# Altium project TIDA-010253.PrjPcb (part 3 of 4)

## Sheet Driver and output.SchDoc
size 558 x 431 mm; Date: Not shown in title block; ApprovedBy: Not shown in title block; CheckedBy: Not shown in title block; Author: Not shown in title block; CompanyName: Not shown in title block; Engineer: Not shown in title block; Organization: Not shown in title block; Address1: Not shown in title block; Address2: Not shown in title block; Address3: Not shown in title block; Address4: Not shown in title block; DocumentNumber: 1; Revision: Use project parameter SCH_Rev; SheetNumber: 4; SheetTotal: 7; PageSetup: Record=PageOptions¦CenterHorizontal=True¦CenterVertical=True¦PrintScale=1.00¦XCorrection=1.00¦YCorrection=1.00¦PrintKind=0¦BorderSize=5000000¦LeftOffset=0¦BottomOffset=0¦Orientation=2¦PaperLength=1000¦PaperWidth=1000¦Scale=100¦PaperSource=15¦PrintQuality=600¦MediaType=1¦DitherType=10¦PaperKind=Letter¦PrintScaleMode=1
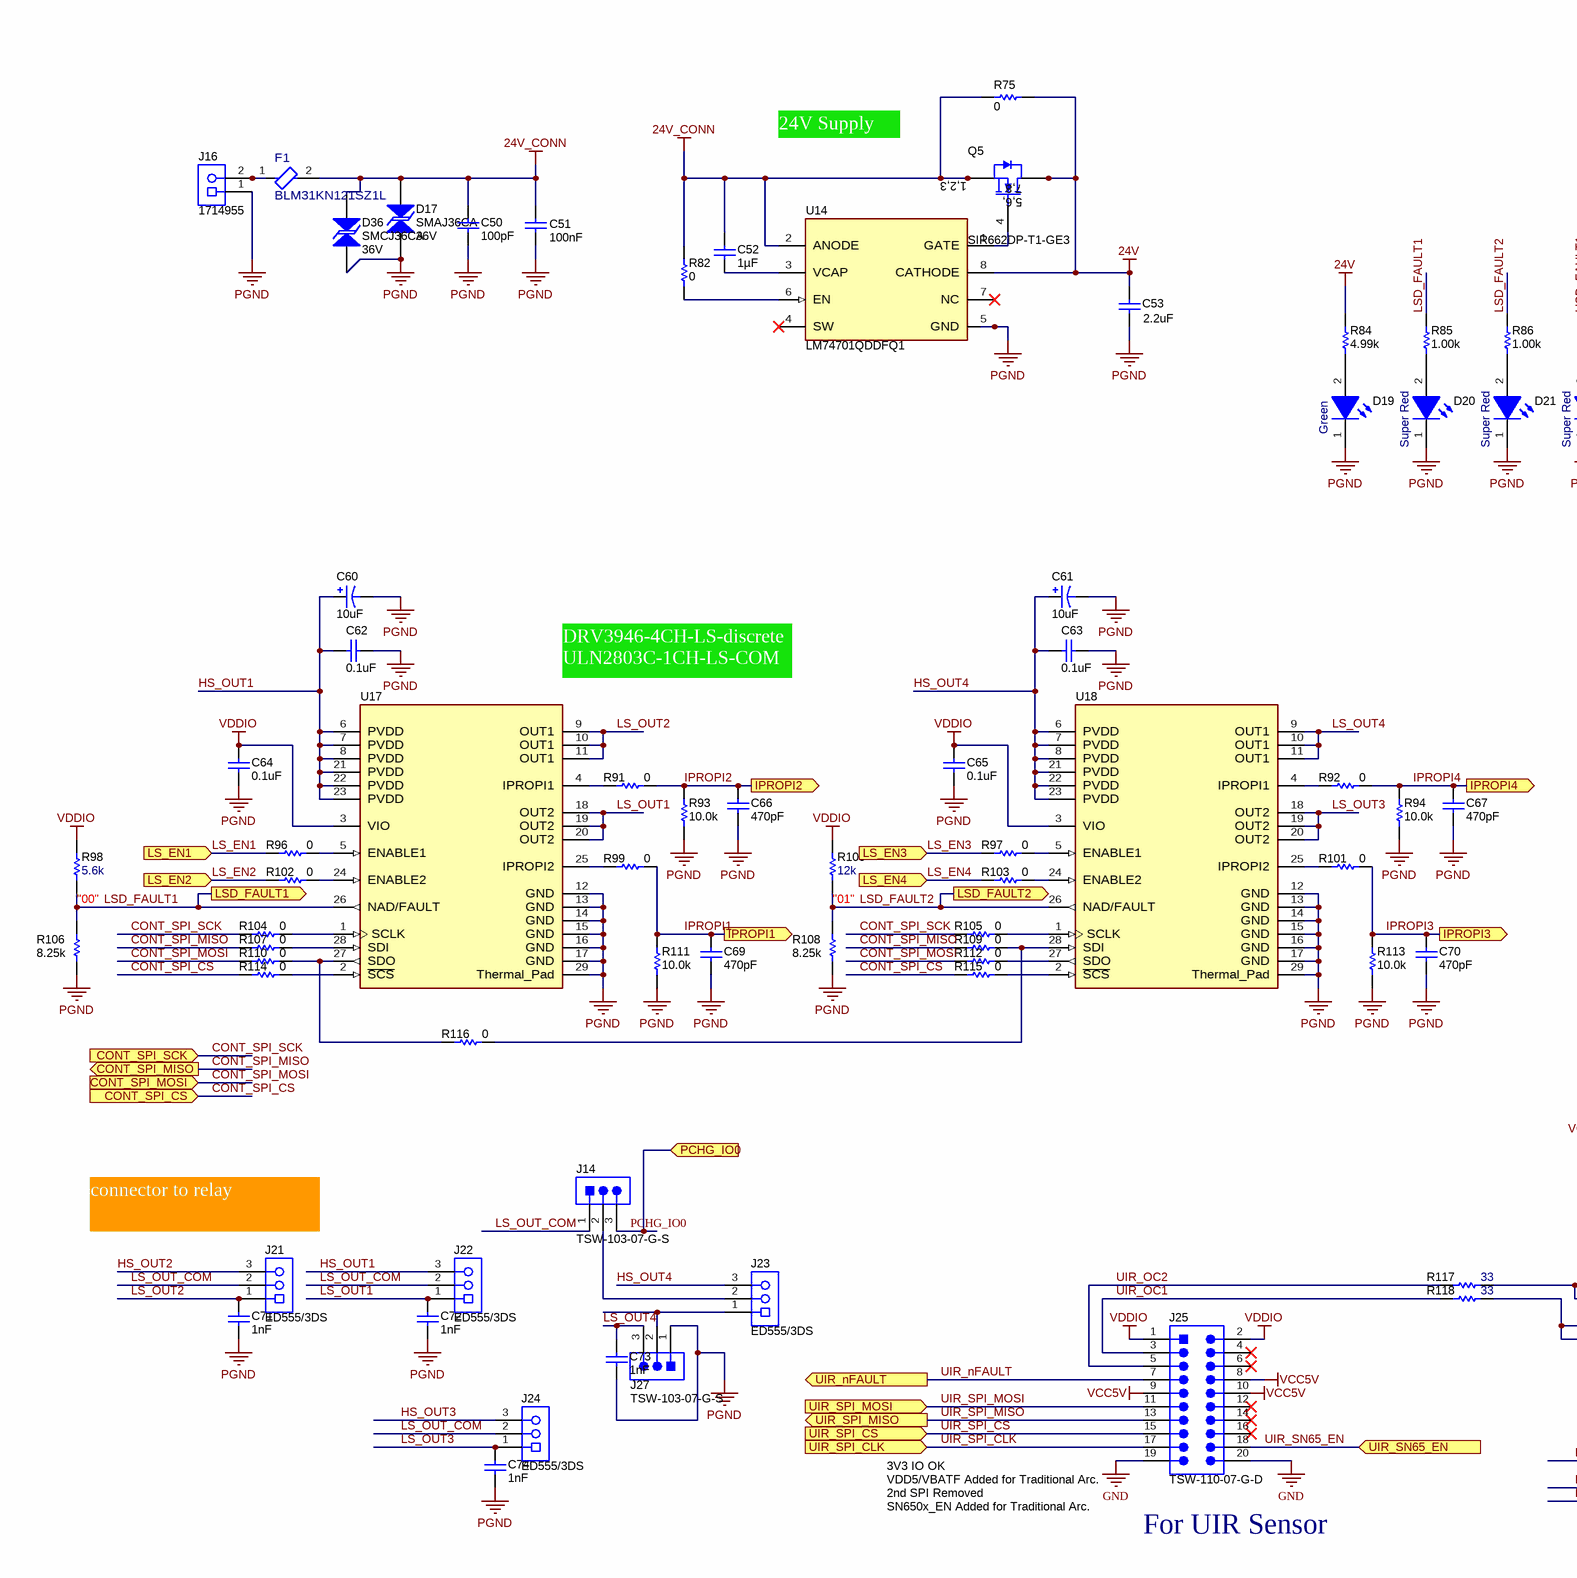
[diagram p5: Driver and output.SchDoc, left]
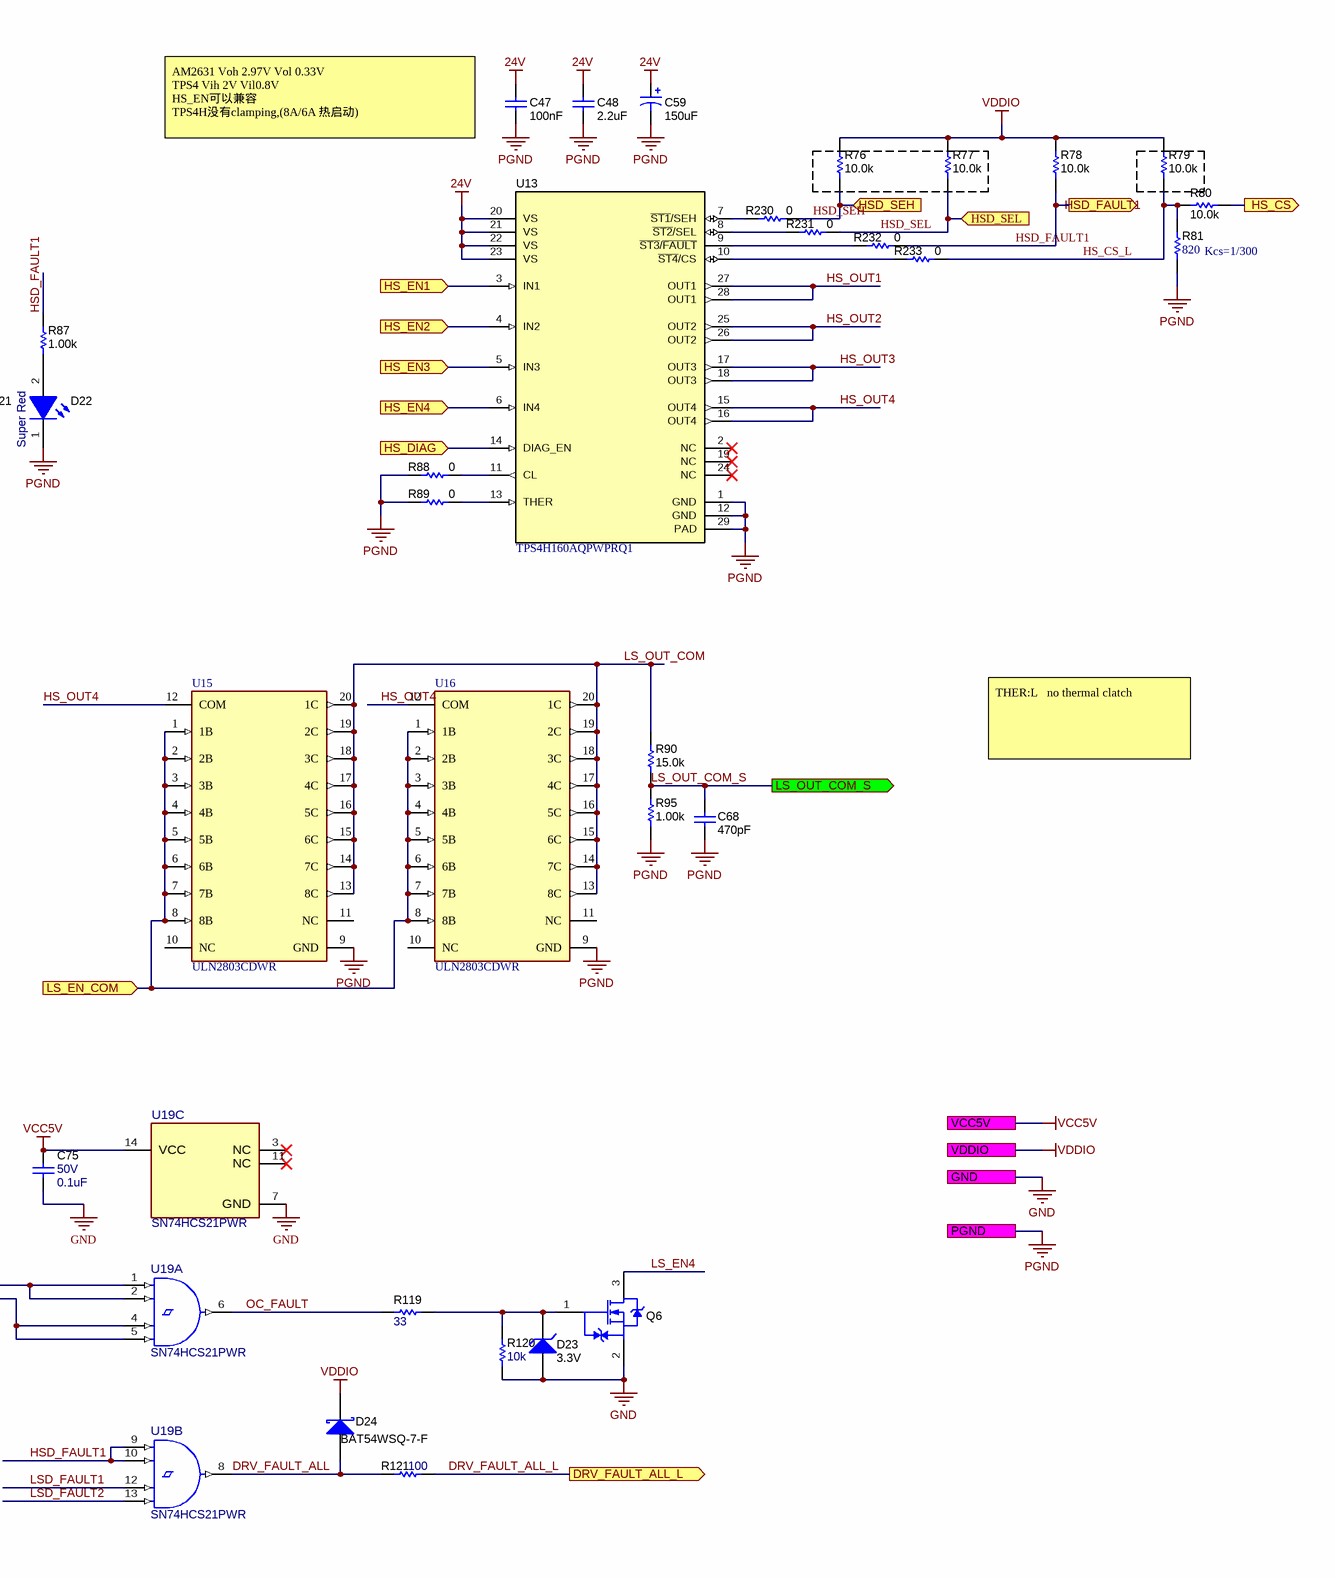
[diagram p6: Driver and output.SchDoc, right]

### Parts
C47  Cap_F: 100nF  [0603L]  (hidden comment: 885012206095)
C48  ValueDisplayed: 2.2uF  [0805L]  (hidden comment: C2012X6S1H225K125AB)
C50  ValueDisplayed: 100pF  [0603L]  (hidden comment: C0603C101J5GAC)
C51  Cap_F: 100nF  [0603L]  (hidden comment: 885012206095)
C52  Cap_F: 1µF  [0603L]  (hidden comment: CGA3E1X7R1E105K080AD)
C53  ValueDisplayed: 2.2uF  [0805L]  (hidden comment: C2012X6S1H225K125AB)
C59  ValueDisplayed: 150uF  [SM_RADIAL_G]  (hidden comment: EEE-FK1H151P)
C60  ValueDisplayed: 10uF  [SM_RADIAL_D]  (hidden comment: EEE-FK1H100P)
C61  ValueDisplayed: 10uF  [SM_RADIAL_D]  (hidden comment: EEE-FK1H100P)
C62  ValueDisplayed: 0.1uF  [0402L]  (hidden comment: C1005X7R1H104K050BE)
C63  ValueDisplayed: 0.1uF  [0402L]  (hidden comment: C1005X7R1H104K050BE)
C64  ValueDisplayed: 0.1uF  [0402L]  (hidden comment: C1005X7R1H104K050BE)
C65  ValueDisplayed: 0.1uF  [0402L]  (hidden comment: C1005X7R1H104K050BE)
C66  ValueDisplayed: 470pF  [0402L]  (hidden comment: GRM155R71H471KA01D)
C67  ValueDisplayed: 470pF  [0402L]  (hidden comment: GRM155R71H471KA01D)
C68  ValueDisplayed: 470pF  [0402L]  (hidden comment: GRM155R71H471KA01D)
C69  ValueDisplayed: 470pF  [0402L]  (hidden comment: GRM155R71H471KA01D)
C70  ValueDisplayed: 470pF  [0402L]  (hidden comment: GRM155R71H471KA01D)
C71  Cap_F: 1nF  [0603L]  (hidden comment: C0603C102J5RACAUTO)
C72  Cap_F: 1nF  [0603L]  (hidden comment: C0603C102J5RACAUTO)
C73  Cap_F: 1nF  [0603L]  (hidden comment: C0603C102J5RACAUTO)
C74  Cap_F: 1nF  [0603L]  (hidden comment: C0603C102J5RACAUTO)
C75  VDC_V: 50V  ValueDisplayed: 0.1uF  [0402]  (hidden comment: GCM155R71H104KE02D)
D17  SMAJ36CA  value 36V  [SMA_Bi]
D19  value Green  [WL-SMCW_GREEN]  (hidden comment: 150060VS75000)
D20  value Super Red  [WL-SMCW_RED]  (hidden comment: 150060SS75000)
D21  value Super Red  [WL-SMCW_RED]  (hidden comment: 150060SS75000)
D22  value Super Red  [WL-SMCW_RED]  (hidden comment: 150060SS75000)
D23  value 3.3V  [SOD-323]  (hidden comment: SZMM3Z3V3ST1G)
D24  BAT54WSQ-7-F  [SOD-323]
D36  SMCJ36CA  value 36V  [SMC_Bi]
F1  BLM31KN121SZ1L  [FP-BLM31KN121SZ1L_1206-MFG]
J14  TSW-103-07-G-S  [TSW-103-07-G-S]
J16  1714955  [Phoenix_1714955]
J21  ED555/3DS  [TERM_BLK_ED555-3DS]
J22  ED555/3DS  [TERM_BLK_ED555-3DS]
J23  ED555/3DS  [TERM_BLK_ED555-3DS]
J24  ED555/3DS  [TERM_BLK_ED555-3DS]
J25  TSW-110-07-G-D  [TSW-110-07-G-D]
J27  TSW-103-07-G-S  [TSW-103-07-G-S]
Q5  SIR662DP-T1-GE3  [PowerPAK_SO-8]
Q6  RJU003N03FRAT106  [SOT-323]  (value not drawn)
R75  ValueDisplayed: 0  [2512]  (hidden comment: RMC1JPTE)
R76  ValueDisplayed: 10.0k  [0402L]  (hidden comment: RC0402FR-0710KL)
R77  ValueDisplayed: 10.0k  [0402L]  (hidden comment: RC0402FR-0710KL)
R78  ValueDisplayed: 10.0k  [0402L]  (hidden comment: RC0402FR-0710KL)
R79  ValueDisplayed: 10.0k  [0402L]  (hidden comment: RC0402FR-0710KL)
R80  ValueDisplayed: 10.0k  [0402L]  (hidden comment: RC0402FR-0710KL)
R81  ValueDisplayed: 820  [0402]  (hidden comment: RC0402FR-07820RL)
R82  ValueDisplayed: 0  [0402L]  (hidden comment: CRCW04020000Z0EDHP)
R84  ValueDisplayed: 4.99k  [0603L]  (hidden comment: CRCW06034K99FKEAC)
R85  ValueDisplayed: 1.00k  [0402L]  (hidden comment: RC0402FR-071KL)
R86  ValueDisplayed: 1.00k  [0402L]  (hidden comment: RC0402FR-071KL)
R87  ValueDisplayed: 1.00k  [0402L]  (hidden comment: RC0402FR-071KL)
R88  ValueDisplayed: 0  [0402L]  (hidden comment: CRCW04020000Z0EDHP)
R89  ValueDisplayed: 0  [0402L]  (hidden comment: CRCW04020000Z0EDHP)
R90  ValueDisplayed: 15.0k  [0402L]  (hidden comment: RC0402FR-0715KL)
R91  ValueDisplayed: 0  [0402L]  (hidden comment: CRCW04020000Z0EDHP)
R92  ValueDisplayed: 0  [0402L]  (hidden comment: CRCW04020000Z0EDHP)
R93  ValueDisplayed: 10.0k  [0402L]  (hidden comment: RC0402FR-0710KL)
R94  ValueDisplayed: 10.0k  [0402L]  (hidden comment: RC0402FR-0710KL)
R95  ValueDisplayed: 1.00k  [0402L]  (hidden comment: RC0402FR-071KL)
R96  ValueDisplayed: 0  [0402L]  (hidden comment: CRCW04020000Z0EDHP)
R97  ValueDisplayed: 0  [0402L]  (hidden comment: CRCW04020000Z0EDHP)
R98  ValueDisplayed: 5.6k  [0402L]  (hidden comment: CRCW04025K60JNED)
R99  ValueDisplayed: 0  [0402L]  (hidden comment: CRCW04020000Z0EDHP)
R100  ValueDisplayed: 12k  [0402L]  (hidden comment: CRCW040212K0JNED)
R101  ValueDisplayed: 0  [0402L]  (hidden comment: CRCW04020000Z0EDHP)
R102  ValueDisplayed: 0  [0402L]  (hidden comment: CRCW04020000Z0EDHP)
R103  ValueDisplayed: 0  [0402L]  (hidden comment: CRCW04020000Z0EDHP)
R104  ValueDisplayed: 0  [0402L]  (hidden comment: CRCW04020000Z0EDHP)
R105  ValueDisplayed: 0  [0402L]  (hidden comment: CRCW04020000Z0EDHP)
R106  ValueDisplayed: 8.25k  [0402L]  (hidden comment: CRCW04028K25FKED)
R107  ValueDisplayed: 0  [0402L]  (hidden comment: CRCW04020000Z0EDHP)
R108  ValueDisplayed: 8.25k  [0402L]  (hidden comment: CRCW04028K25FKED)
R109  ValueDisplayed: 0  [0402L]  (hidden comment: CRCW04020000Z0EDHP)
R110  ValueDisplayed: 0  [0402L]  (hidden comment: CRCW04020000Z0EDHP)
R111  ValueDisplayed: 10.0k  [0402L]  (hidden comment: RC0402FR-0710KL)
R112  ValueDisplayed: 0  [0402L]  (hidden comment: CRCW04020000Z0EDHP)
R113  ValueDisplayed: 10.0k  [0402L]  (hidden comment: RC0402FR-0710KL)
R114  ValueDisplayed: 0  [0402L]  (hidden comment: CRCW04020000Z0EDHP)
R115  ValueDisplayed: 0  [0402L]  (hidden comment: CRCW04020000Z0EDHP)
R116  ValueDisplayed: 0  [0402L]  (hidden comment: CRCW04020000Z0EDHP)
R117  ValueDisplayed: 33  [0402]  (hidden comment: CRCW040233R0JNED)
R118  ValueDisplayed: 33  [0402]  (hidden comment: CRCW040233R0JNED)
R119  ValueDisplayed: 33  [0402]  (hidden comment: CRCW040233R0JNED)
R120  ValueDisplayed: 10k  [0402]  (hidden comment: CRCW040210K0JNED)
R121  ValueDisplayed: 100  [0402]  (hidden comment: CRCW0402100RJNED)
R230  ValueDisplayed: 0  [0402L]  (hidden comment: CRCW04020000Z0EDHP)
R231  ValueDisplayed: 0  [0402L]  (hidden comment: CRCW04020000Z0EDHP)
R232  ValueDisplayed: 0  [0402L]  (hidden comment: CRCW04020000Z0EDHP)
R233  ValueDisplayed: 0  [0402L]  (hidden comment: CRCW04020000Z0EDHP)
U13  TPS4H160AQPWPRQ1  [PWP0028C_N]
U14  LM74701QDDFQ1  [DDF0008A-MFG]
U15  ULN2803CDWR  [FP-DW0020A-MFG]
U16  ULN2803CDWR  [FP-DW0020A-MFG]
U17  DRV3946-Q1  [PWP0028R-MFG]  (value not drawn)
U18  DRV3946-Q1  [PWP0028R-MFG]  (value not drawn)
U19  SN74HCS21PWR  [PW0014A-MFG]  (parts A,B,C of 3)

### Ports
CONT_SPI_CS (in), CONT_SPI_MISO (out), CONT_SPI_MOSI (in), CONT_SPI_SCK (in), DRV_FAULT_ALL_L (out), GND, HS_CS (out), HS_DIAG (in), HS_EN1 (in), HS_EN2 (in), HS_EN3 (in), HS_EN4 (in), HSD_FAULT1 (out), HSD_SEH (in), HSD_SEL (in), IPROPI1 (out), IPROPI2 (out), IPROPI3 (out), IPROPI4 (out), LS_EN1 (in), LS_EN2 (in), LS_EN3 (in), LS_EN4 (in), LS_EN_COM (in), LS_OUT_COM_S (out), LSD_FAULT1 (out), LSD_FAULT2 (out), PCHG_IO0 (in), PGND, UIR_nFAULT (out), UIR_SN65_EN (in), UIR_SPI_CLK (in), UIR_SPI_CS (in), UIR_SPI_MISO (out), UIR_SPI_MOSI (in), VCC5V, VDDIO

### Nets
24V: C47.1 C48.1 C53.1 C59.1(+) Q5.5(D) Q5.6(D) Q5.7(D) Q5.8(D) Q5.9(D) R75.2 R84.2 U13.20(VS) U13.21(VS) U13.22(VS) U13.23(VS) U14.8(CATHODE)
24V_CONN: C50.1 C51.1 C52.1 D17.2 D36.2 F1.2 Q5.1(S) Q5.2(S) Q5.3(S) R75.1 R82.2 U14.2(ANODE)
GND: C75.2 D23.2(A) J25.19 J25.20 Q6.2(S) R120.1 U19.7(GND) ; port GND
PGND: C47.2 C48.2 C50.2 C51.2 C53.2 C59.2(-) C60.2(-) C61.2(-) C62.1 C63.1 C64.2 C65.2 C66.2 C67.2 C68.2 C69.2 C70.2 C71.1 C72.1 C73.1 C74.1 D17.1 D19.1(K) D20.1(K) D21.1(K) D22.1(K) D36.1 J16.1 J27.1 R81.1 R88.1 R89.1 R93.1 R94.1 R95.1 R106.1 R108.1 R111.1 R113.1 U13.1(GND) U13.12(GND) U13.29(PAD) U14.5(GND) U15.9(GND) U16.9(GND) U17.12(GND) U17.13(GND) U17.14(GND) U17.15(GND) U17.16(GND) U17.17(GND) U17.29(Thermal_Pad) U18.12(GND) U18.13(GND) U18.14(GND) U18.15(GND) U18.16(GND) U18.17(GND) U18.29(Thermal_Pad) ; port PGND
VCC5V: C75.1 J25.8 J25.9 J25.10 U19.14(VCC) ; port VCC5V
VDDIO: C64.1 C65.1 D24.1(K) J25.1 J25.2 R76.2 R77.2 R78.2 R79.2 R98.2 R100.2 U17.3(VIO) U18.3(VIO) ; port VDDIO
CONT_SPI_CS: R114.1 R115.1 ; port CONT_SPI_CS
CONT_SPI_MISO: R107.1 R109.1 ; port CONT_SPI_MISO
CONT_SPI_MOSI: R110.1 R112.1 ; port CONT_SPI_MOSI
CONT_SPI_SCK: R104.1 R105.1 ; port CONT_SPI_SCK
DRV_FAULT_ALL: D24.2(A) R121.1 U19.8(2Y)
DRV_FAULT_ALL_L: R121.2 ; port DRV_FAULT_ALL_L
HS_CS: R80.1 ; port HS_CS
HS_CS_L: R79.1 R80.2 R81.2 R233.2
HS_DIAG: U13.14(DIAG_EN) ; port HS_DIAG
HS_EN1: U13.3(IN1) ; port HS_EN1
HS_EN2: U13.4(IN2) ; port HS_EN2
HS_EN3: U13.5(IN3) ; port HS_EN3
HS_EN4: U13.6(IN4) ; port HS_EN4
HS_OUT1: C60.1(+) C62.2 J22.3 U13.27(OUT1) U13.28(OUT1) U17.6(PVDD) U17.7(PVDD) U17.8(PVDD) U17.21(PVDD) U17.22(PVDD) U17.23(PVDD)
HS_OUT2: J21.3 U13.25(OUT2) U13.26(OUT2)
HS_OUT3: J24.3 U13.17(OUT3) U13.18(OUT3)
HS_OUT4: C61.1(+) C63.2 J23.3 U13.15(OUT4) U13.16(OUT4) U15.12(COM) U16.12(COM) U18.6(PVDD) U18.7(PVDD) U18.8(PVDD) U18.21(PVDD) U18.22(PVDD) U18.23(PVDD)
HSD_FAULT1: R78.1 R87.2 R232.2 U19.9(2A) U19.10(2B) ; port HSD_FAULT1
HSD_SEH: R76.1 R230.2 ; port HSD_SEH
HSD_SEL: R77.1 R231.2 ; port HSD_SEL
IPROPI1: C69.1 R99.2 R111.2 ; port IPROPI1
IPROPI2: C66.1 R91.2 R93.2 ; port IPROPI2
IPROPI3: C70.1 R101.2 R113.2 ; port IPROPI3
IPROPI4: C67.1 R92.2 R94.2 ; port IPROPI4
LS_EN1: R96.1 ; port LS_EN1
LS_EN2: R102.1 ; port LS_EN2
LS_EN3: R97.1 ; port LS_EN3
LS_EN4: Q6.3(D) R103.1 ; port LS_EN4
LS_EN_COM: U15.1(1B) U15.2(2B) U15.3(3B) U15.4(4B) U15.5(5B) U15.6(6B) U15.7(7B) U15.8(8B) U16.1(1B) U16.2(2B) U16.3(3B) U16.4(4B) U16.5(5B) U16.6(6B) U16.7(7B) U16.8(8B) ; port LS_EN_COM
LS_OUT1: C72.2 J22.1 U17.18(OUT2) U17.19(OUT2) U17.20(OUT2)
LS_OUT2: C71.2 J21.1 U17.9(OUT1) U17.10(OUT1) U17.11(OUT1)
LS_OUT3: C74.2 J24.1 U18.18(OUT2) U18.19(OUT2) U18.20(OUT2)
LS_OUT4: C73.2 J27.3 U18.9(OUT1) U18.10(OUT1) U18.11(OUT1)
LS_OUT_COM: J14.1 J21.2 J22.2 J24.2 R90.2 U15.13(8C) U15.14(7C) U15.15(6C) U15.16(5C) U15.17(4C) U15.18(3C) U15.19(2C) U15.20(1C) U16.13(8C) U16.14(7C) U16.15(6C) U16.16(5C) U16.17(4C) U16.18(3C) U16.19(2C) U16.20(1C)
LS_OUT_COM_S: C68.1 R90.1 R95.2 ; port LS_OUT_COM_S
LSD_FAULT1: R85.2 R98.1 R106.2 U17.26(NAD/FAULT) U19.12(2C) ; port LSD_FAULT1
LSD_FAULT2: R86.2 R100.1 R108.2 U18.26(NAD/FAULT) U19.13(2D) ; port LSD_FAULT2
OC_FAULT: R119.2 U19.6(1Y)
PCHG_IO0: J14.3 ; port PCHG_IO0
UIR_nFAULT: J25.7 ; port UIR_nFAULT
UIR_OC1: J25.3 R118.1
UIR_OC2: J25.5 R117.1
UIR_SN65_EN: J25.18 ; port UIR_SN65_EN
UIR_SPI_CLK: J25.17 ; port UIR_SPI_CLK
UIR_SPI_CS: J25.15 ; port UIR_SPI_CS
UIR_SPI_MISO: J25.13 ; port UIR_SPI_MISO
UIR_SPI_MOSI: J25.11 ; port UIR_SPI_MOSI
NetC52_2: C52.2 U14.3(VCAP)
NetD19_2: D19.2(A) R84.1
NetD20_2: D20.2(A) R85.1
NetD21_2: D21.2(A) R86.1
NetD22_2: D22.2(A) R87.1
NetD23_1: D23.1(K) Q6.1(G) R119.1 R120.2
NetF1_1: F1.1 J16.2
NetJ14_2: J14.2 J23.2
NetJ23_1: J23.1 J27.2
NetQ5_4: Q5.4(G) U14.1(GATE)
NetR82_1: R82.1 U14.6(EN)
NetR88_2: R88.2 U13.11(CL)
NetR89_2: R89.2 U13.13(THER)
NetR91_1: R91.1 U17.4(IPROPI1)
NetR92_1: R92.1 U18.4(IPROPI1)
NetR96_2: R96.2 U17.5(ENABLE1)
NetR97_2: R97.2 U18.5(ENABLE1)
NetR99_1: R99.1 U17.25(IPROPI2)
NetR101_1: R101.1 U18.25(IPROPI2)
NetR102_2: R102.2 U17.24(ENABLE2)
NetR103_2: R103.2 U18.24(ENABLE2)
NetR104_2: R104.2 U17.1(SCLK)
NetR105_2: R105.2 U18.1(SCLK)
NetR107_2: R107.2 U17.28(SDI)
NetR109_2: R109.2 R116.2 U18.28(SDI)
NetR110_2: R110.2 R116.1 U17.27(SDO)
NetR112_2: R112.2 U18.27(SDO)
NetR114_2: R114.2 U17.2(~{SCS})
NetR115_2: R115.2 U18.2(~{SCS})
NetR117_2: R117.2 U19.1(1A) U19.2(1B)
NetR118_2: R118.2 U19.4(1C) U19.5(1D)
NetR230_1: R230.1 U13.7(~{ST1}/SEH)
NetR231_1: R231.1 U13.8(~{ST2}/SEL)
NetR232_1: R232.1 U13.9(~{ST3}/~{FAULT})
NetR233_1: R233.1 U13.10(~{ST4}/CS)

Not connected (* = marked no-connect by the designer): J25 4* 6* 12* 14* 16*; U13 2(NC)* 19(NC)* 24(NC)*; U14 4(SW)* 7(NC)*; U15 10(NC) 11(NC); U16 10(NC) 11(NC); U19 3(NC)* 11(NC)*

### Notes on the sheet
- 24V Supply
- (near C47) AM2631 Voh 2.97V Vol 0.33V
  TPS4 Vih 2V Vil0.8V
  HS_EN可以兼容
  TPS4H没有clamping,(8A/6A 热启动)
- Kcs=1/300
- DRV3946-4CH-LS-discrete
  ULN2803C-1CH-LS-COM
- THER:L   no thermal clatch
- (near R98) "00"
- (near R100) "01"
- (near J21) connector to relay
- 3V3 IO OK
- 2nd SPI Removed
- VDD5/VBATF Added for Traditional Arc.
- SN650x_EN Added for Traditional Arc.
- (near J25) For UIR Sensor

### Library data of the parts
C47 C51 = CMP-0006837-4: CAP, CERM, 0.1 uF, 50 V, +/- 10%, X7R, 0603; Manufacturer: Wurth Elektronik; TaMin_C: -55°C; Polarized: N; SizeAreaWB_mm2: 4.68; Value1: Unknown; U/M: EA; Value: 0.1uF; TaMax_C: 125°C; SizeZ_mm: 1; SizeX_mm: 1.6; SizeY_mm: 0.8; Cap_Case: 0603; Value2: 50V; SizeArea_mm2: 1.28; AEC Category: Q200
C48 C53 = CMP-0007857-1: CAP, CERM, 2.2 uF, 50 V, +/- 10%, X6S, 0805; Manufacturer: TDK; TaMin_C: -55°C; ESR_ohm: 3.66m; Polarized: N; SizeAreaWB_mm2: 6.75; Value1: 0.00366 ohm; U/M: EA; Value: 2.2uF; TaMax_C: 105°C; SizeZ_mm: 1.45; SizeX_mm: 2; SizeY_mm: 1.25; Cap_Case: 0805; Value2: 50V; SizeArea_mm2: 2.5; Cap_F: 2.2µF; IRMS_A: 3.41207A; AEC Category: Q200
C50 = CMP-0006840-4: CAP, CERM, 100 pF, 50 V, +/- 5%, C0G/NP0, 0603; Manufacturer: Kemet; TaMin_C: -55°C; Polarized: N; SizeAreaWB_mm2: 4.68; Value1: Unknown; U/M: EA; Value: 100pF; TaMax_C: 125°C; SizeZ_mm: 1; SizeX_mm: 1.6; SizeY_mm: 0.8; Cap_Case: 0603; Value2: 50V; SizeArea_mm2: 1.28; AEC Category: Q200
C52 = CMP-0082523-1: CAP, CERM, 1 µF, 25 V,+/- 10%, X7R, AEC-Q200 Grade 1, 0603; Manufacturer: TDK; SizeAreaWB_mm2: 4.68; SizeArea_mm2: 1.28; AEC Qualified: Y; AEC Category: Q200; Value: 1uF; TaMax_C: 125°C; SizeZ_mm: 1; Polarized: N; TaMin_C: -55°C; VDC_V: 25V; SizeY_mm: 0.8; U/M: EA; SizeX_mm: 1.6; Cap_Case: 0603
C59 = CMP-0011178-2: CAP, AL, 150 uF, 50 V, +/- 20%, 0.18 ohm, AEC-Q200 Grade 2, SMD; Manufacturer: Panasonic; TaMin_C: -55°C; ESR_ohm: 0.18; Polarized: Y; SizeAreaWB_mm2: 172.2; U/M: EA; Value: 150uF; TaMax_C: 105°C; SizeZ_mm: 10.2; SizeX_mm: 12; SizeY_mm: 10.3; Cap_Case: G; Value2: 50V; SizeArea_mm2: 123.6; CompType: Capacitor; Cap_F: 150µF; IRMS_A: 670mA; AEC Grade: 2; AEC Category: Q200
C60 C61 = CMP-0011175-2: CAP, AL, 10 uF, 50 V, +/- 20%, 0.88 ohm, AEC-Q200 Grade 2, SMD; Manufacturer: Panasonic; TaMin_C: -55°C; ESR_ohm: 0.88; Polarized: Y; SizeAreaWB_mm2: 84.28; U/M: EA; Value: 10uF; TaMax_C: 105°C; SizeZ_mm: 5.4; SizeX_mm: 7.8; SizeY_mm: 6.6; Cap_Case: D; Value2: 50V; SizeArea_mm2: 51.48; CompType: Capacitor; Cap_F: 10µF; IRMS_A: 165mA; AEC Grade: 2; AEC Category: Q200
C62-C65 = CMP-0064946-2: CAP, CERM, 0.1 uF, 50 V,+/- 10%, X7R, 0402; Manufacturer: TDK; TaMin_C: -55°C; Polarized: N; SizeAreaWB_mm2: 3; Value1: Unknown; U/M: EA; Value: 0.1uF; TaMax_C: 125°C; SizeZ_mm: 0.6; SizeX_mm: 1; SizeY_mm: 0.5; Cap_Case: 0402; Value2: 50V; Cap_F: 100nF; AEC Category: Q200
C66-C70 = CMP-0006691-2: CAP, CERM, 470 pF, 50 V, +/- 10%, X7R, 0402; Manufacturer: MuRata; TaMin_C: -55°C; Polarized: N; SizeAreaWB_mm2: 3; Value1: Unknown; U/M: EA; Value: 470pF; TaMax_C: 125°C; SizeZ_mm: 0.6; SizeX_mm: 1; SizeY_mm: 0.5; Cap_Case: 0402; Value2: 50V; AEC Category: Q200
C71-C74 = CMP-0006844-4: CAP, CERM, 1000 pF, 50 V, +/- 5%, X7R, AEC-Q200 Grade 1, 0603; Manufacturer: Kemet; TaMin_C: -55°C; Polarized: N; SizeAreaWB_mm2: 4.68; Value1: Unknown; U/M: EA; Value: 1000pF; TaMax_C: 125°C; SizeZ_mm: 1; SizeX_mm: 1.6; SizeY_mm: 0.8; Cap_Case: 0603; Value2: 50V; SizeArea_mm2: 1.28; AEC Qualified: Y; AEC Category: Q200
C75 = CMP-0006356-2: CAP, CERM, 0.1 uF, 50 V, +/- 10%, X7R, AEC-Q200 Grade 1, 0402; Manufacturer: MuRata; TaMin_C: -55°C; Polarized: N; SizeAreaWB_mm2: 3; Value1: Unknown; U/M: EA; Value: 0.1uF; TaMax_C: 125°C; SizeZ_mm: 0.6; SizeX_mm: 1; SizeY_mm: 0.5; AEC Qualified: Y; Cap_F: 100nF; AEC Category: Q200
D17 = CMP-0085017-1: Diode, TVS, Bi, 36 V, 58.1 Vc, 400 W, 6.9 A, SMA (non-polarized); Manufacturer: Littelfuse; RJA_CperW: 120; SizeAreaWB_mm2: 32.368125; Vbr_Min: 40V; AEC Qualified: N; SizeArea_mm2: 13.068125; Vc: 58.1V; SizeZ_mm: 2.65; Ipp: 6.9A; AEC Category: Q101; SizeY_mm: 2.575; SizeX_mm: 5.075; Ppk: 400W; Vbr_Max: 44.2V
D19 = CMP-0002894-2: LED, Green, SMD; Manufacturer: Wurth Elektronik; Type: AlInGaP; Value2: 2V; Io_A: 20mA; Value1: W
D20-D22 = CMP-0002893-1: LED, Super Red, SMD; Manufacturer: Wurth Elektronik; Io_A: 20mA; Value1: W; U/M: EA; Vf_V: 1.9V; Type: AlInGaP
D23 = CMP-0085730-1: Diode, Zener, 3.3 V, 300 mW, AEC-Q101, SOD-323; Manufacturer: ON Semiconductor; RJA_CperW: 416; AEC Qualified: Y; SizeArea_mm2: 3.645; SizeX_mm: 2.7; SizeY_mm: 1.35; SizeZ_mm: 1; AEC Category: Q101; SizeAreaWB_mm2: 8.695; Power_W: 300mW; Value1: 0.3W
D24 = CMP-0081199-2: Diode, Schottky, 30 V, 0.1 A, AEC-Q101, SOD-323; Manufacturer: Diodes Inc.; Value1: 0.1A; SizeArea_mm2: 3.645; Value: 30V; Vf_V: 1V; Io_A: 100mA; TJmax_C: 150°C; SizeY_mm: 1.35; SizeX_mm: 2.7; AEC Qualified: Y; SizeAreaWB_mm2: 8.695; SizeZ_mm: 1; AEC Category: Q101
D36 = CMP-0005697-3: Diode, TVS, Bi, 36 V, 58.1 Vc, SMC; Manufacturer: Littelfuse; Ppk: 1.5kW; Vbr_Min: 40V; SizeX_mm: 8.13; SizeZ_mm: 2.6; SizeAreaWB_mm2: 83.2686; RJA_CperW: 75; AEC Category: Q101; Vbr_Max: 44.2V; SizeArea_mm2: 50.5686; Ipp: 25.9A; Vc: 58.1V; AEC Qualified: N; Value1: 1500W; SizeY_mm: 6.22
F1 = CMP-0091575-1: Chip Ferrite Bead, 1206, 120Ω @ 100MHz, 0.009Ω, 25%, 6A; Manufacturer: Murata; SizeZ_mm: 1.8mm; DCR_ohm: 9m; AEC Grade: Grade 1; AEC Qualified: Yes
J14 J27 = CMP-0075407-2: Header, 100mil, 3x1, Gold, TH; Manufacturer: Samtec; Pitch_mm: 2.54; Cert_VDE: N; Gender: Male; Cert_CSA: Y; Voltage_V: 550V; Green_REACh: Passed; Current_A: 6.3A; Green_Lifecycle: Active; Row_Count: 1
J16 = CMP-0055505-1: Terminal Block, 2x1, 6.35mm, Green, TH; Manufacturer: Phoenix Contact; CNHeader: FALSE; Shrouded: Y; Gender: Female; Row_Count: 1; Pitch_mm: 6.35; CT: TRUE
J21-J24 = CMP-0074916-1: Terminal Block, 3.5mm Pitch, 3x1, TH; Manufacturer: On-Shore Technology; Cert_VDE: Y; CNHeader: False; Current_A: 6A; Green_Lifecycle: Active; Shrouded: N; Gender: Female; Green_REACh: Passed; Voltage_V: 150V; Row_Count: 1; Pitch_mm: 3.5; ContactFinish: Brass; CT: True
J25 = CMP-0075421-2: Header, 100mil, 10x2, Gold, TH; Manufacturer: Samtec; Pitch_mm: 2.54; Cert_VDE: N; Gender: Male; Cert_CSA: Y; Voltage_V: 550V; Green_REACh: Passed; Current_A: 6.3A; Green_Lifecycle: Active; Row_Count: 2
Q5 = CMP-0000870-1: MOSFET, N-CH, 60 V, 60 A, PowerPAK SO-8; Alternate Manufacturer: None; Manufacturer: Vishay-Semiconductor; SizeZ_mm: 1.12; ChType: N; Value2: 96 nC; Value1: 0.002; VdsMax_V: 60V; SizeX_mm: 5.99; SizeY_mm: 4.9; Vgs_V: 2.5V; Value: 60V; Rdson45_ohm: 2.7m; SizeArea_mm2: 29.351; AEC Category: Q101; IdsMax_A: 60A; SizeAreaWB_mm2: 55.131; U/M: EA; QgTyp_nC: 96
Q6 = CMP-0067562-1: MOSFET, N-CH, 30 V, 0.3 A, AEC-Q101, SOT-323; Alternate Manufacturer: None; Manufacturer: Rohm; Rdson45_ohm: 1.1; SizeAreaWB_mm2: 10.24; Vgs_V: 12V; Value1: 1.1 ohm; VdsMax_V: 30V; U/M: EA; Value: 30V; IdsMax_A: 3dA; SizeX_mm: 2.2; Value2: ? nC; SizeArea_mm2: 4.84; ChType: N; AEC Qualified: Y; AEC Category: Q101
R75 = CMP-0080698-1: RES, 0, 0%, 1 W, AEC-Q200 Grade 0, 2512; Manufacturer: Kamaya; SizeAreaWB_mm2: 43.16; SizeArea_mm2: 20.16; AEC Qualified: Y; AEC Category: Q200; Value: 0; SizeZ_mm: 0.71; SizeY_mm: 3.2; Power_W: 1W; SizeX_mm: 6.3
R76-R80 R93 R94 R111 R113 = CMP-0078669-1: RES, 10.0 k, 1%, 0.063 W, 0402; Manufacturer: Yageo America; Power_W: 63mW; Green_Lifecycle: Active; TempCo: 100 ppm/C; Value_Code: 10k0; Green_REACh: Passed; Value: 10.0k; EIA_Code: E96; Res_ohm: 10k; SizeX_mm: 1; SizeY_mm: 0.5; SizeZ_mm: 0.6; Value2: 0.063W; AEC Qualified: N; AEC Category: Q200
R81 = CMP-0026743-1: RES, 820, 1%, 0.063 W, 0402; Manufacturer: Yageo America; Power_W: 63mW; TempCo: 100 ppm/C; Value_Code: 820R; U/M: EA; Value: 820; SizeX_mm: 1; SizeY_mm: 0.5; SizeZ_mm: 0.6; Value2: 0.063W; AEC Qualified: N; VDC_V: 50V; AEC Category: Q200
R82 R88 R89 R91 R92 R96 R97 R99 R101-R105 R107 R109 R110 R112 R114-R116 R230-R233 = CMP-0081856-1: RES, 0, 0%, 0.2 W, AEC-Q200 Grade 0, 0402; Manufacturer: Vishay-Dale; SizeAreaWB_mm2: 3; SizeArea_mm2: 0.5; AEC Qualified: Y; AEC Category: Q200; Value: 0; SizeZ_mm: 0.6; Power_W: 200mW; VDC_V: 50V; Value2: 0.2W; SizeX_mm: 1
R84 = CMP-0082533-1: RES, 4.99 k, 1%, 0.1 W, 0603; Manufacturer: Vishay-Dale; Power_W: 100mW; TempCo: 100 ppm/C; SizeAreaWB_mm2: 4.68; Value_Code: 4k99; Value: 4.99k; EIA_Code: E96; SizeX_mm: 1.6; SizeY_mm: 0.8; SizeZ_mm: 1; Value2: 0.1W; SizeArea_mm2: 1.28; AEC Qualified: N; VDC_V: 75V; AEC Category: Q200
R85-R87 R95 = CMP-0026725-1: RES, 1.00 k, 1%, 0.0625 W, 0402; Manufacturer: Yageo America; Power_W: 62.5mW; TempCo: 100 ppm/C; Value_Code: 1k00; U/M: EA; Value: 1.00k; EIA_Code: E96; Res_ohm: 1k; SizeX_mm: 1; SizeY_mm: 0.5; SizeZ_mm: 0.6; AEC Qualified: N; VDC_V: 50V; AEC Category: Q200
R90 = CMP-0078583-1: RES, 15.0 k, 1%, 0.063 W, 0402; Manufacturer: Yageo America; Power_W: 63mW; Green_Lifecycle: Active; TempCo: 100 ppm/C; Value_Code: 15k0; Green_REACh: Passed; Value: 15.0k; EIA_Code: E96; Res_ohm: 15k; SizeX_mm: 1; SizeY_mm: 0.5; SizeZ_mm: 0.6; Value2: 0.063W; AEC Qualified: N; AEC Category: Q200
R98 = CMP-0026952-5: RES, 5.6 k, 5%, 0.063 W, AEC-Q200 Grade 0, 0402; Manufacturer: Vishay-Dale; Power_W: 63mW; TempCo: 200 ppm/C; Value_Code: 5k60; Value: 5.6k; EIA_Code: E24; SizeX_mm: 1; SizeY_mm: 0.5; SizeZ_mm: 0.6; Value2: 0.063W; AEC Qualified: Y; VDC_V: 50V; AEC Category: Q200; AEC Grade: 0
R100 = CMP-0026834-3: RES, 12 k, 5%, 0.063 W, AEC-Q200 Grade 0, 0402; Manufacturer: Vishay-Dale; Power_W: 63mW; TempCo: 200 ppm/C; Value_Code: 12k0; Value: 12k; EIA_Code: E24; SizeX_mm: 1; SizeY_mm: 0.5; SizeZ_mm: 0.6; Value2: 0.063W; AEC Qualified: Y; VDC_V: 50V; AEC Category: Q200; AEC Grade: 0
R106 R108 = CMP-0026589-2: RES, 8.25 k, 1%, 0.063 W, AEC-Q200 Grade 0, 0402; Manufacturer: Vishay-Dale; Power_W: 63mW; TempCo: 100 ppm/C; Value_Code: 8k25; Value: 8.25k; EIA_Code: E96; SizeX_mm: 1; SizeY_mm: 0.5; SizeZ_mm: 0.6; Value2: 0.063W; AEC Qualified: Y; VDC_V: 50V; AEC Category: Q200; AEC Grade: 0
R117-R119 = CMP-0026908-3: RES, 33, 5%, 0.063 W, AEC-Q200 Grade 0, 0402; Manufacturer: Vishay-Dale; Power_W: 63mW; TempCo: 200 ppm/C; Value_Code: 33R0; Value: 33; EIA_Code: E24; SizeX_mm: 1; SizeY_mm: 0.5; SizeZ_mm: 0.6; Value2: 0.063W; AEC Qualified: Y; VDC_V: 50V; AEC Category: Q200; AEC Grade: 0
R120 = CMP-0026825-5: RES, 10 k, 5%, 0.063 W, AEC-Q200 Grade 0, 0402; Manufacturer: Vishay-Dale; Power_W: 63mW; TempCo: 200 ppm/C; Value_Code: 10k0; Value: 10k; EIA_Code: E24; SizeX_mm: 1; SizeY_mm: 0.5; SizeZ_mm: 0.6; Value2: 0.063W; AEC Qualified: Y; VDC_V: 50V; AEC Category: Q200; AEC Grade: 0
R121 = CMP-0026824-3: RES, 100, 5%, 0.063 W, AEC-Q200 Grade 0, 0402; Manufacturer: Vishay-Dale; Power_W: 63mW; TempCo: 200 ppm/C; Value_Code: 100R; Value: 100; EIA_Code: E24; SizeX_mm: 1; SizeY_mm: 0.5; SizeZ_mm: 0.6; Value2: 0.063W; AEC Qualified: Y; VDC_V: 50V; AEC Category: Q200; AEC Grade: 0
U13 = CMP-0073695-3: 40-V/160-mohm Quad Channels Smart High-Side Switch, PWP0028C (TSSOP-28); Manufacturer: Texas Instruments; SizeX_mm: 6.4; SizeY_mm: 9.7; CompType: IC; SizeZ_mm: 1.2; SizeArea_mm2: 62.08; SizeAreaWB_mm2: 98.28; AEC Category: Q200; AEC Qualified: Y
U14 = CMP-0090057-1: Low IQ Reverse Battery Protection Ideal Diode Controller with Integrated VDS Clamp; Manufacturer: Texas Instruments; Standoff Height: 0mm; TaMin_C: -40°C; Nominal Supply Current: 80uA; SizeZ_mm: 1.1mm; Number Of Outputs: 1; TaMax_C: +125°C; TJmax_C: +150°C; AEC Grade: Grade 1; AEC Qualified: Yes; Max Supply Voltage: 65V; Min Supply Voltage: 3.2V
U15 U16 = CMP-04912-000113-1: 50-V, EIGHT-CHANNEL DARLINGTON A
U17 U18 = CMP-0093137-1: 12-V Automotive Fully Integrated Solenoid/ Contactor Driver with PWM current regulation, Clamping function & Functional Safety 2 Channels, Single wire Low side interface; Manufacturer: Texas Instruments; Number Of Outputs: 2; AEC Grade: Grade 1; AEC Qualified: Yes; Nominal Supply Current: 5mA; SizeZ_mm: 1.2mm; Switching Frequency: 0.5-25kHz; Standoff Height: 0.05mm; Max Supply Voltage: 35V
U19 = CMP-0001652-1: Dual 4-Input AND Gates with Schmitt-Trigger Inputs; Manufacturer: Texas Instruments; SizeZ_mm: 1.2mm; AEC Qualified: No; Max Supply Voltage: 6V; Min Supply Voltage: 2V; Nominal Supply Current: 0.1uA; Number Of Inputs: 4; Number Of Outputs: 1; PositionCount: 2; Propagation Delay: 8ns; Standoff Height: 0.05mm; TaMax_C: +125°C; TaMin_C: -40°C; TJmax_C: +150°C

## Sheet BCU Board_CAN485.SchDoc
size A2; Date: Not shown in title block; ApprovedBy: Not shown in title block; CheckedBy: Not shown in title block; Author: Not shown in title block; CompanyName: Not shown in title block; Engineer: Not shown in title block; Organization: Not shown in title block; Address1: Not shown in title block; Address2: Not shown in title block; Address3: Not shown in title block; Address4: Not shown in title block; DocumentNumber: 1; Revision: Use project parameter SCH_Rev; SheetNumber: 2; SheetTotal: 7; PageSetup: Record=PageOptions¦CenterHorizontal=True¦CenterVertical=True¦PrintScale=0.69¦XCorrection=1.00¦YCorrection=1.00¦PrintKind=0¦BorderSize=5000000¦LeftOffset=0¦BottomOffset=0¦Orientation=2¦PaperLength=1000¦PaperWidth=1000¦Scale=100¦PaperSource=15¦PrintQuality=600¦MediaType=1¦DitherType=10¦PaperKind=Letter¦PrintScaleMode=1
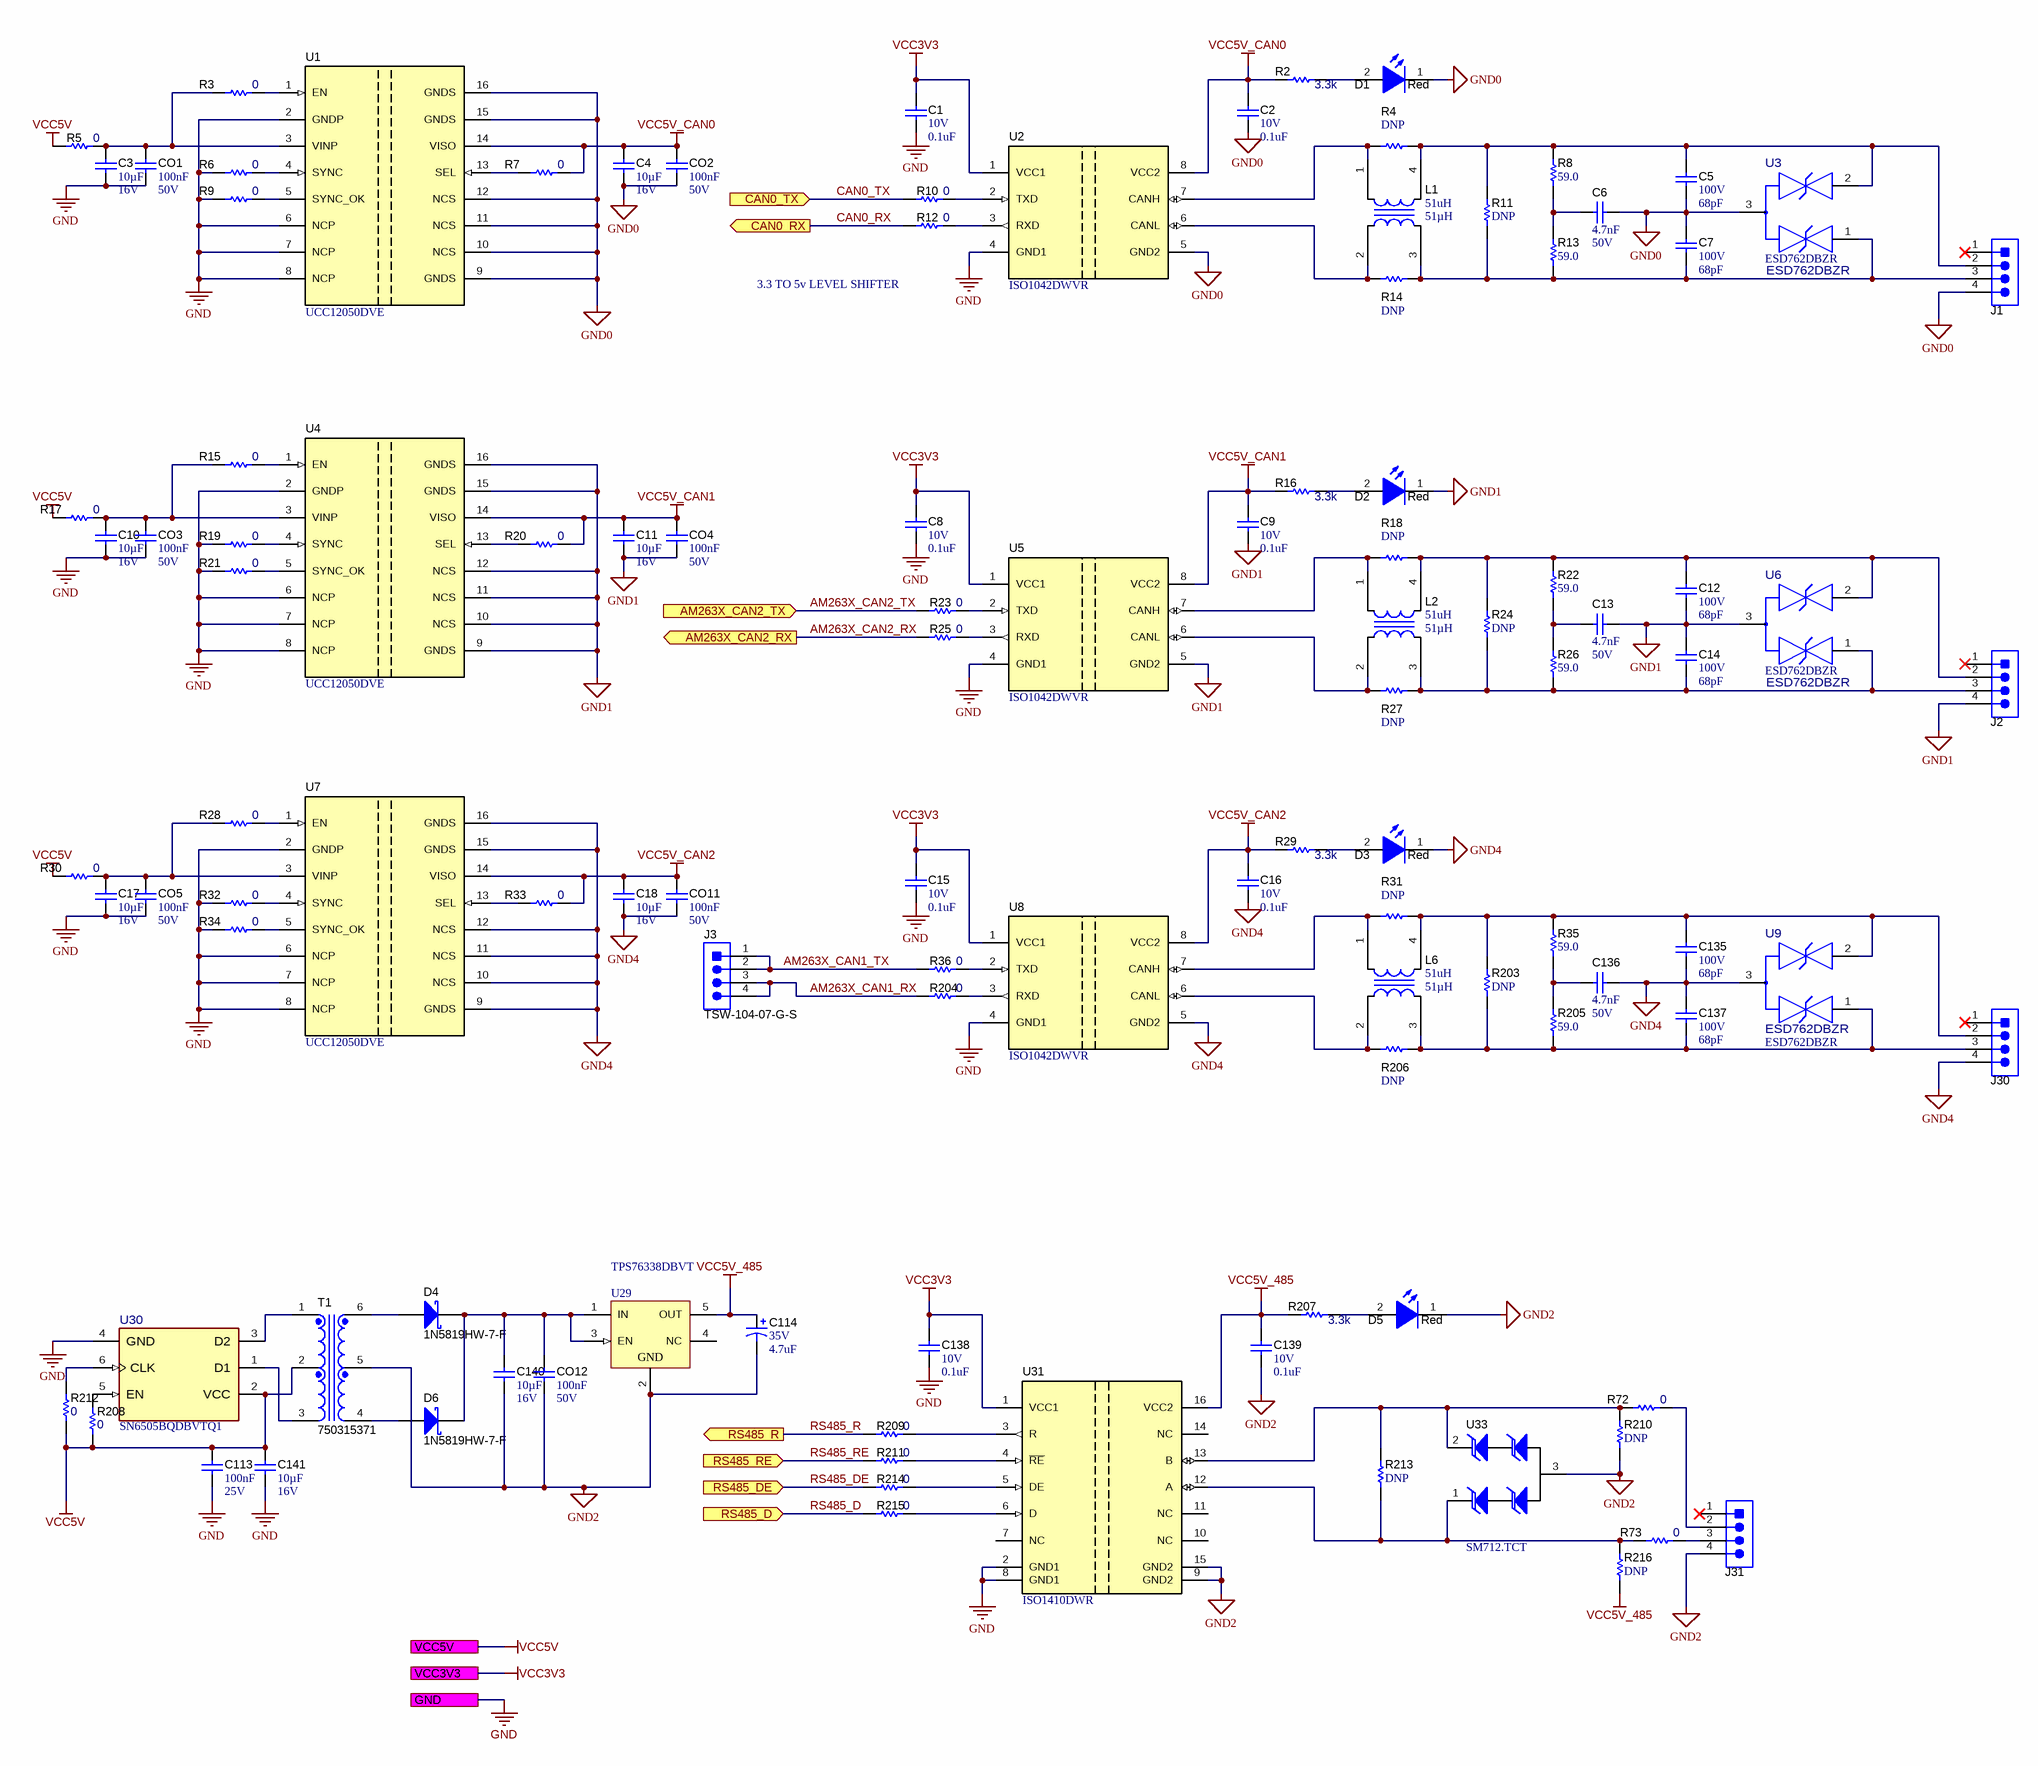
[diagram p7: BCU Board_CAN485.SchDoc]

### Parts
C1  VDC_V: 10V  ValueDisplayed: 0.1uF  [0402]  (hidden comment: GCM155R71A104KA55D)
C2  VDC_V: 10V  ValueDisplayed: 0.1uF  [0402]  (hidden comment: GCM155R71A104KA55D)
C3  Cap_F: 10µF  VDC_V: 16V  [0805_HV]  (hidden comment: CL21B106KOQNNNE)
C4  Cap_F: 10µF  VDC_V: 16V  [0805_HV]  (hidden comment: CL21B106KOQNNNE)
C5  VDC_V: 100V  ValueDisplayed: 68pF  [0603]  (hidden comment: GRM1885C2A680JA01D)
C6  Cap_F: 4.7nF  VDC_V: 50V  [0603]  (hidden comment: GRM188R71H472KA01D)
C7  VDC_V: 100V  ValueDisplayed: 68pF  [0603]  (hidden comment: GRM1885C2A680JA01D)
C8  VDC_V: 10V  ValueDisplayed: 0.1uF  [0402]  (hidden comment: GCM155R71A104KA55D)
C9  VDC_V: 10V  ValueDisplayed: 0.1uF  [0402]  (hidden comment: GCM155R71A104KA55D)
C10  Cap_F: 10µF  VDC_V: 16V  [0805_HV]  (hidden comment: CL21B106KOQNNNE)
C11  Cap_F: 10µF  VDC_V: 16V  [0805_HV]  (hidden comment: CL21B106KOQNNNE)
C12  VDC_V: 100V  ValueDisplayed: 68pF  [0603]  (hidden comment: GRM1885C2A680JA01D)
C13  Cap_F: 4.7nF  VDC_V: 50V  [0603]  (hidden comment: GRM188R71H472KA01D)
C14  VDC_V: 100V  ValueDisplayed: 68pF  [0603]  (hidden comment: GRM1885C2A680JA01D)
C15  VDC_V: 10V  ValueDisplayed: 0.1uF  [0402]  (hidden comment: GCM155R71A104KA55D)
C16  VDC_V: 10V  ValueDisplayed: 0.1uF  [0402]  (hidden comment: GCM155R71A104KA55D)
C17  Cap_F: 10µF  VDC_V: 16V  [0805_HV]  (hidden comment: CL21B106KOQNNNE)
C18  Cap_F: 10µF  VDC_V: 16V  [0805_HV]  (hidden comment: CL21B106KOQNNNE)
C113  Cap_F: 100nF  VDC_V: 25V  [0603]  (hidden comment: 06033C104JAT2A)
C114  VDC_V: 35V  ValueDisplayed: 4.7uF  [6032-28]  (hidden comment: TPSC475K035R0600)
C135  VDC_V: 100V  ValueDisplayed: 68pF  [0603]  (hidden comment: GRM1885C2A680JA01D)
C136  Cap_F: 4.7nF  VDC_V: 50V  [0603]  (hidden comment: GRM188R71H472KA01D)
C137  VDC_V: 100V  ValueDisplayed: 68pF  [0603]  (hidden comment: GRM1885C2A680JA01D)
C138  VDC_V: 10V  ValueDisplayed: 0.1uF  [0402]  (hidden comment: GCM155R71A104KA55D)
C139  VDC_V: 10V  ValueDisplayed: 0.1uF  [0402]  (hidden comment: GCM155R71A104KA55D)
C140  Cap_F: 10µF  VDC_V: 16V  [0805_HV]  (hidden comment: CL21B106KOQNNNE)
C141  Cap_F: 10µF  VDC_V: 16V  [0805_HV]  (hidden comment: CL21B106KOQNNNE)
CO1  Cap_F: 100nF  VDC_V: 50V  [0805_HV]  (hidden comment: 08055C104JAT2A)
CO2  Cap_F: 100nF  VDC_V: 50V  [0805_HV]  (hidden comment: 08055C104JAT2A)
CO3  Cap_F: 100nF  VDC_V: 50V  [0805_HV]  (hidden comment: 08055C104JAT2A)
CO4  Cap_F: 100nF  VDC_V: 50V  [0805_HV]  (hidden comment: 08055C104JAT2A)
CO5  Cap_F: 100nF  VDC_V: 50V  [0805_HV]  (hidden comment: 08055C104JAT2A)
CO11  Cap_F: 100nF  VDC_V: 50V  [0805_HV]  (hidden comment: 08055C104JAT2A)
CO12  Cap_F: 100nF  VDC_V: 50V  [0805_HV]  (hidden comment: 08055C104JAT2A)
D1  value Red  [WL-SMCW_RED]  (hidden comment: 150060RS75000)
D2  value Red  [WL-SMCW_RED]  (hidden comment: 150060RS75000)
D3  value Red  [WL-SMCW_RED]  (hidden comment: 150060RS75000)
D4  1N5819HW-7-F  [SOD-123]
D5  value Red  [WL-SMCW_RED]  (hidden comment: 150060RS75000)
D6  1N5819HW-7-F  [SOD-123]
J1  70551-0038  [Molex_70551-0038]  (value not drawn)
J2  70551-0038  [Molex_70551-0038]  (value not drawn)
J3  TSW-104-07-G-S  [TSW-104-07-G-S]
J30  70551-0038  [Molex_70551-0038]  (value not drawn)
J31  70551-0038  [Molex_70551-0038]  (value not drawn)
L1  value 51uH  ValueDisplayed: 51µH  [ACT45B_NoSilk]  (hidden comment: ACT45B-510-2P-TL003)
L2  value 51uH  ValueDisplayed: 51µH  [ACT45B_NoSilk]  (hidden comment: ACT45B-510-2P-TL003)
L6  value 51uH  ValueDisplayed: 51µH  [ACT45B_NoSilk]  (hidden comment: ACT45B-510-2P-TL003)
R2  ValueDisplayed: 3.3k  [0402]  (hidden comment: CRCW04023K30JNED)
R3  ValueDisplayed: 0  [0603]  (hidden comment: CRCW06030000Z0EA)
R4  ValueDisplayed: DNP  [0402]  (hidden comment: CRCW04020000Z0EDHP)
R5  ValueDisplayed: 0  [0603]  (hidden comment: CRCW06030000Z0EA)
R6  ValueDisplayed: 0  [0603]  (hidden comment: CRCW06030000Z0EA)
R7  ValueDisplayed: 0  [0603]  (hidden comment: CRCW06030000Z0EA)
R8  ValueDisplayed: 59.0  [1206]  (hidden comment: CRCW120659R0FKEA)
R9  ValueDisplayed: 0  [0603]  (hidden comment: CRCW06030000Z0EA)
R10  ValueDisplayed: 0  [0603]  (hidden comment: CRCW06030000Z0EA)
R11  ValueDisplayed: DNP  [2512]  (hidden comment: CRCW2512120RFKEG)
R12  ValueDisplayed: 0  [0603]  (hidden comment: CRCW06030000Z0EA)
R13  ValueDisplayed: 59.0  [1206]  (hidden comment: CRCW120659R0FKEA)
R14  ValueDisplayed: DNP  [0402]  (hidden comment: CRCW04020000Z0EDHP)
R15  ValueDisplayed: 0  [0603]  (hidden comment: CRCW06030000Z0EA)
R16  ValueDisplayed: 3.3k  [0402]  (hidden comment: CRCW04023K30JNED)
R17  ValueDisplayed: 0  [0603]  (hidden comment: CRCW06030000Z0EA)
R18  ValueDisplayed: DNP  [0402]  (hidden comment: CRCW04020000Z0EDHP)
R19  ValueDisplayed: 0  [0603]  (hidden comment: CRCW06030000Z0EA)
R20  ValueDisplayed: 0  [0603]  (hidden comment: CRCW06030000Z0EA)
R21  ValueDisplayed: 0  [0603]  (hidden comment: CRCW06030000Z0EA)
R22  ValueDisplayed: 59.0  [1206]  (hidden comment: CRCW120659R0FKEA)
R23  ValueDisplayed: 0  [0603]  (hidden comment: CRCW06030000Z0EA)
R24  ValueDisplayed: DNP  [2512]  (hidden comment: CRCW2512120RFKEG)
R25  ValueDisplayed: 0  [0603]  (hidden comment: CRCW06030000Z0EA)
R26  ValueDisplayed: 59.0  [1206]  (hidden comment: CRCW120659R0FKEA)
R27  ValueDisplayed: DNP  [0402]  (hidden comment: CRCW04020000Z0EDHP)
R28  ValueDisplayed: 0  [0603]  (hidden comment: CRCW06030000Z0EA)
R29  ValueDisplayed: 3.3k  [0402]  (hidden comment: CRCW04023K30JNED)
R30  ValueDisplayed: 0  [0603]  (hidden comment: CRCW06030000Z0EA)
R31  ValueDisplayed: DNP  [0402]  (hidden comment: CRCW04020000Z0EDHP)
R32  ValueDisplayed: 0  [0603]  (hidden comment: CRCW06030000Z0EA)
R33  ValueDisplayed: 0  [0603]  (hidden comment: CRCW06030000Z0EA)
R34  ValueDisplayed: 0  [0603]  (hidden comment: CRCW06030000Z0EA)
R35  ValueDisplayed: 59.0  [1206]  (hidden comment: CRCW120659R0FKEA)
R36  ValueDisplayed: 0  [0603]  (hidden comment: CRCW06030000Z0EA)
R72  ValueDisplayed: 0  [0603]  (hidden comment: CRCW06030000Z0EA)
R73  ValueDisplayed: 0  [0603]  (hidden comment: CRCW06030000Z0EA)
R203  ValueDisplayed: DNP  [2512]  (hidden comment: CRCW2512120RFKEG)
R204  ValueDisplayed: 0  [0603]  (hidden comment: CRCW06030000Z0EA)
R205  ValueDisplayed: 59.0  [1206]  (hidden comment: CRCW120659R0FKEA)
R206  ValueDisplayed: DNP  [0402]  (hidden comment: CRCW04020000Z0EDHP)
R207  ValueDisplayed: 3.3k  [0402]  (hidden comment: CRCW04023K30JNED)
R208  ValueDisplayed: 0  [0603]  (hidden comment: CRCW06030000Z0EA)
R209  ValueDisplayed: 0  [0603]  (hidden comment: CRCW06030000Z0EA)
R210  ValueDisplayed: DNP  [0805_HV]  (hidden comment: RR1220P-911-D)
R211  ValueDisplayed: 0  [0603]  (hidden comment: CRCW06030000Z0EA)
R212  ValueDisplayed: 0  [0603]  (hidden comment: CRCW06030000Z0EA)
R213  ValueDisplayed: DNP  [0805_HV]  (hidden comment: ESR10EZPF1200)
R214  ValueDisplayed: 0  [0603]  (hidden comment: CRCW06030000Z0EA)
R215  ValueDisplayed: 0  [0603]  (hidden comment: CRCW06030000Z0EA)
R216  ValueDisplayed: DNP  [0805_HV]  (hidden comment: RR1220P-911-D)
T1  750315371  [Wurth_750315371]
U1  UCC12050DVE  [DVE0016A]
U2  ISO1042DWVR  [DWV0008A]
U3  ESD762DBZR  [DBZ0003A-MFG]
U4  UCC12050DVE  [DVE0016A]
U5  ISO1042DWVR  [DWV0008A]
U6  ESD762DBZR  [DBZ0003A-MFG]
U7  UCC12050DVE  [DVE0016A]
U8  ISO1042DWVR  [DWV0008A]
U9  ESD762DBZR  [DBZ0003A-MFG]
U29  TPS76338DBVT  [DBV0005A_N]
U30  SN6505BQDBVTQ1  [DBV0006A-MFG]
U31  ISO1410DWR  [DW0016B_HV]
U33  PartNumber: SM712.TCT  [SOT-23]  (hidden comment: ESDS552)

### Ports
AM263X_CAN2_RX (out), AM263X_CAN2_TX (in), CAN0_RX (out), CAN0_TX (in), GND, RS485_D (in), RS485_DE (in), RS485_R (out), RS485_RE (in), VCC3V3, VCC5V

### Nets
GND: C1.1 C3.2 C8.1 C10.2 C15.1 C17.2 C113.2 C138.1 C141.2 CO1.2 CO3.2 CO5.2 R6.1 R9.1 R19.1 R21.1 R32.1 R34.1 U1.2(GNDP) U1.6(NCP) U1.7(NCP) U1.8(NCP) U2.4(GND1) U4.2(GNDP) U4.6(NCP) U4.7(NCP) U4.8(NCP) U5.4(GND1) U7.2(GNDP) U7.6(NCP) U7.7(NCP) U7.8(NCP) U8.4(GND1) U30.4(GND) U31.2(GND1) U31.8(GND1) ; port GND
GND0: C2.1 C4.2 C5.2 C6.1 C7.1 CO2.2 D1.1(K) J1.4 U1.9(GNDS) U1.10(NCS) U1.11(NCS) U1.12(NCS) U1.15(GNDS) U1.16(GNDS) U2.5(GND2) U3.3(GND)
GND1: C9.1 C11.2 C12.2 C13.1 C14.1 CO4.2 D2.1(K) J2.4 U4.9(GNDS) U4.10(NCS) U4.11(NCS) U4.12(NCS) U4.15(GNDS) U4.16(GNDS) U5.5(GND2) U6.3(GND)
GND2: C114.2(-) C139.1 C140.2 CO12.2 D5.1(K) J31.4 R210.1 T1.5 U29.2(GND) U31.9(GND2) U31.15(GND2) U33.3
GND4: C16.1 C18.2 C135.2 C136.1 C137.1 CO11.2 D3.1(K) J30.4 U7.9(GNDS) U7.10(NCS) U7.11(NCS) U7.12(NCS) U7.15(GNDS) U7.16(GNDS) U8.5(GND2) U9.3(GND)
VCC3V3: C1.2 C8.2 C15.2 C138.2 U2.1(VCC1) U5.1(VCC1) U8.1(VCC1) U31.1(VCC1) ; port VCC3V3
VCC5V: C113.1 C141.1 R5.1 R17.1 R30.1 R208.1 R212.1 T1.2 U30.2(VCC) ; port VCC5V
VCC5V_485: C114.1(+) C139.2 R207.1 R216.1 U29.5(OUT) U31.16(VCC2)
VCC5V_CAN0: C2.2 C4.1 CO2.1 R2.1 R7.2 U1.14(VISO) U2.8(VCC2)
VCC5V_CAN1: C9.2 C11.1 CO4.1 R16.1 R20.2 U4.14(VISO) U5.8(VCC2)
VCC5V_CAN2: C16.2 C18.1 CO11.1 R29.1 R33.2 U7.14(VISO) U8.8(VCC2)
AM263X_CAN1_RX: J3.3 J3.4 R204.1
AM263X_CAN1_TX: J3.1 J3.2 R36.1
AM263X_CAN2_RX: R25.1 ; port AM263X_CAN2_RX
AM263X_CAN2_TX: R23.1 ; port AM263X_CAN2_TX
CAN0_RX: R12.1 ; port CAN0_RX
CAN0_TX: R10.1 ; port CAN0_TX
RS485_D: R215.1 ; port RS485_D
RS485_DE: R214.1 ; port RS485_DE
RS485_R: R209.1 ; port RS485_R
RS485_RE: R211.1 ; port RS485_RE
NetC3_1: C3.1 CO1.1 R3.1 R5.2 U1.3(VINP)
NetC5_1: C5.1 J1.2 L1.4 R4.1 R8.2 R11.2 U3.2(2_IO)
NetC6_2: C6.2 R8.1 R13.2
NetC7_2: C7.2 J1.3 L1.3 R11.1 R13.1 R14.1 U3.1(1_IO)
NetC10_1: C10.1 CO3.1 R15.1 R17.2 U4.3(VINP)
NetC12_1: C12.1 J2.2 L2.4 R18.1 R22.2 R24.2 U6.2(2_IO)
NetC13_2: C13.2 R22.1 R26.2
NetC14_2: C14.2 J2.3 L2.3 R24.1 R26.1 R27.1 U6.1(1_IO)
NetC17_1: C17.1 CO5.1 R28.1 R30.2 U7.3(VINP)
NetC135_1: C135.1 J30.2 L6.4 R31.1 R35.2 R203.2 U9.2(2_IO)
NetC136_2: C136.2 R35.1 R205.2
NetC137_2: C137.2 J30.3 L6.3 R203.1 R205.1 R206.1 U9.1(1_IO)
NetC140_1: C140.1 CO12.1 D4.1(K) D6.1(K) U29.1(IN) U29.3(EN)
NetD1_2: D1.2(A) R2.2
NetD2_2: D2.2(A) R16.2
NetD3_2: D3.2(A) R29.2
NetD4_2: D4.2(A) T1.6
NetD5_2: D5.2(A) R207.2
NetD6_2: D6.2(A) T1.4
NetJ31_2: J31.2 R72.2
NetJ31_3: J31.3 R73.2
NetL1_1: L1.1 R4.2 U2.7(CANH)
NetL1_2: L1.2 R14.2 U2.6(CANL)
NetL2_1: L2.1 R18.2 U5.7(CANH)
NetL2_2: L2.2 R27.2 U5.6(CANL)
NetL6_1: L6.1 R31.2 U8.7(CANH)
NetL6_2: L6.2 R206.2 U8.6(CANL)
NetR3_2: R3.2 U1.1(EN)
NetR6_2: R6.2 U1.4(SYNC)
NetR7_1: R7.1 U1.13(SEL)
NetR9_2: R9.2 U1.5(SYNC_OK)
NetR10_2: R10.2 U2.2(TXD)
NetR12_2: R12.2 U2.3(RXD)
NetR15_2: R15.2 U4.1(EN)
NetR19_2: R19.2 U4.4(SYNC)
NetR20_1: R20.1 U4.13(SEL)
NetR21_2: R21.2 U4.5(SYNC_OK)
NetR23_2: R23.2 U5.2(TXD)
NetR25_2: R25.2 U5.3(RXD)
NetR28_2: R28.2 U7.1(EN)
NetR32_2: R32.2 U7.4(SYNC)
NetR33_1: R33.1 U7.13(SEL)
NetR34_2: R34.2 U7.5(SYNC_OK)
NetR36_2: R36.2 U8.2(TXD)
NetR72_1: R72.1 R210.2 R213.2 U31.13(B) U33.2
NetR73_1: R73.1 R213.1 R216.2 U31.12(A) U33.1
NetR204_2: R204.2 U8.3(RXD)
NetR208_2: R208.2 U30.5(EN)
NetR209_2: R209.2 U31.3(R)
NetR211_2: R211.2 U31.4(~{RE})
NetR212_2: R212.2 U30.6(CLK)
NetR214_2: R214.2 U31.5(DE)
NetR215_2: R215.2 U31.6(D)
NetT1_1: T1.1 U30.3(D2)
NetT1_3: T1.3 U30.1(D1)

Not connected (* = marked no-connect by the designer): J1 1*; J2 1*; J30 1*; J31 1*; U29 4(NC); U31 7(NC) 10(NC) 11(NC) 14(NC)

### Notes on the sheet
- 3.3 TO 5v LEVEL SHIFTER

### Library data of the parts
C1 C2 C8 C9 C15 C16 C138 C139 = CMP-0006350-2: CAP, CERM, 0.1 uF, 10 V, +/- 10%, X7R, AEC-Q200 Grade 1, 0402; Manufacturer: MuRata; TaMin_C: -55°C; Polarized: N; SizeAreaWB_mm2: 3; Value1: Unknown; U/M: EA; Value: 0.1uF; TaMax_C: 125°C; SizeZ_mm: 0.6; SizeX_mm: 1; SizeY_mm: 0.5; AEC Qualified: Y; Cap_F: 100nF; AEC Category: Q200
C3 C4 C10 C11 C17 C18 C140 C141 = CMP-0007995-2: CAP, CERM, 10 uF, 16 V, +/- 10%, X7R, 0805; Manufacturer: Samsung Electro-Mechanics; TaMin_C: -55°C; Polarized: N; SizeAreaWB_mm2: 6.75; Value1: Unknown; U/M: EA; Value: 10uF; TaMax_C: 125°C; SizeZ_mm: 1.45; SizeX_mm: 2; SizeY_mm: 1.25; Cap_Case: 0805; SizeArea_mm2: 2.5; AEC Category: Q200
C5 C7 C12 C14 C135 C137 = CMP-0007280-4: CAP, CERM, 68 pF, 100 V, +/- 5%, C0G/NP0, 0603; Manufacturer: MuRata; TaMin_C: -55°C; Polarized: N; SizeAreaWB_mm2: 4.68; Value1: Unknown; U/M: EA; Value: 68pF; TaMax_C: 125°C; SizeZ_mm: 1; SizeX_mm: 1.6; SizeY_mm: 0.8; SizeArea_mm2: 1.28; AEC Category: Q200
C6 C13 C136 = CMP-0007456-1: CAP, CERM, 4700 pF, 50 V, +/- 10%, X7R, 0603; Manufacturer: MuRata; TaMin_C: -55°C; Polarized: N; SizeAreaWB_mm2: 4.68; Value1: Unknown; U/M: EA; Value: 4700pF; TaMax_C: 125°C; SizeZ_mm: 1; SizeX_mm: 1.6; SizeY_mm: 0.8; SizeArea_mm2: 1.28; AEC Category: Q200
C113 = CMP-0006752-5: CAP, CERM, 0.1 uF, 25 V, +/- 5%, X7R, 0603; Manufacturer: AVX; TaMin_C: -55°C; ESR_ohm: 0.05; Polarized: N; SizeAreaWB_mm2: 4.68; Value1: 0.05 ohm; U/M: EA; Value: 0.1uF; TaMax_C: 125°C; SizeZ_mm: 1; SizeX_mm: 1.6; SizeY_mm: 0.8; SizeArea_mm2: 1.28; AEC Category: Q200
C114 = CMP-0011667-2: CAP, TA, 4.7 uF, 35 V, +/- 10%, 0.6 ohm, SMD; Manufacturer: AVX; TaMin_C: -55°C; ESR_ohm: 6d; Polarized: Y; SizeAreaWB_mm2: 41.6; Value1: 0.6 ohm; U/M: EA; Value: 4.7uF; TaMax_C: 125°C; SizeZ_mm: 2.8; SizeX_mm: 6; SizeY_mm: 3.2; Cap_Case: C; SizeArea_mm2: 19.2; CompType: Capacitor; Cap_F: 4.7µF; IRMS_A: 3.85dA; AEC Category: Q200
CO1-CO5 CO11 CO12 = CMP-0007631-2: CAP, CERM, 0.1 uF, 50 V, +/- 5%, X7R, 0805; Manufacturer: AVX; TaMin_C: -55°C; ESR_ohm: 0.024; Polarized: N; SizeAreaWB_mm2: 6.75; Value1: 0.024 ohm; U/M: EA; Value: 0.1uF; TaMax_C: 125°C; SizeZ_mm: 1.45; SizeX_mm: 2; SizeY_mm: 1.25; Cap_Case: 0805; SizeArea_mm2: 2.5; AEC Category: Q200
D1-D3 D5 = CMP-0002947-3: LED, Red, SMD; Manufacturer: Wurth Elektronik; Value1: 0.072W; Vf_V: 2V; Angle: 140; Tjmax_C: 85°C; Type: AlInGaP; Vr_V: 5V; Io_A: 30mA; Power_TotalModule: 72mW
D4 D6 = CMP-0028360-2: Diode, Schottky, 40 V, 1 A, SOD-123; Manufacturer: Diodes Inc.; Green_Lifecycle: Active; AEC Category: Q101; TJmax_C: 125°C; SizeArea_mm2: 6.545; Vr_V: 40V; Value1: 1A; SizeZ_mm: 1.35; Value: 40V; Vf_V: 450mV; SizeX_mm: 3.85; Green_REACh: Passed; Value2: 0.45V; SizeY_mm: 1.7; SizeAreaWB_mm2: 13.095
J1 J2 J30 J31 = CMP-0055239-1: Header(shrouded), 2.54mm, 4x1, R/A, Gold, TH; Manufacturer: Molex; CNHeader: FALSE; Current_A: 3A; Green_Lifecycle: Active; Shrouded: Y; Gender: Male; Green_REACh: Passed; Voltage_V: 250V; Row_Count: 1; Pitch_mm: 2.54
J3 = CMP-0075409-2: Header, 100mil, 4x1, Gold, TH; Manufacturer: Samtec; Pitch_mm: 2.54; Cert_VDE: N; Gender: Male; Cert_CSA: Y; Voltage_V: 550V; Green_REACh: Passed; Current_A: 6.3A; Green_Lifecycle: Active; Row_Count: 1
L1 L2 L6 = CMP-0076845-1: Coupled inductor, 51 µH, 0.2 A, 1 ohm, AEC-Q200 Grade 0, SMD; Manufacturer: TDK; SizeAreaWB_mm2: 23.1; SizeArea_mm2: 14.4; AEC Qualified: Y; AEC Category: Q200; SizeZ_mm: 3.0; Green_REACh: Passed; AEC Grade: 0; SizeY_mm: 3.2; Green_Lifecycle: Active; DCR_ohm: 1; SizeX_mm: 4.5
R2 R16 R29 R207 = CMP-0026918-5: RES, 3.3 k, 5%, 0.063 W, AEC-Q200 Grade 0, 0402; Manufacturer: Vishay-Dale; Power_W: 63mW; TempCo: 200 ppm/C; Value_Code: 3k30; Value: 3.3k; EIA_Code: E24; SizeX_mm: 1; SizeY_mm: 0.5; SizeZ_mm: 0.6; Value2: 0.063W; AEC Qualified: Y; VDC_V: 50V; AEC Category: Q200; AEC Grade: 0
R3 R5-R7 R9 R10 R12 R15 R17 R19-R21 R23 R25 R28 R30 R32-R34 R36 R72 R73 R204 R208 R209 R211 R212 R214 R215 = CMP-0025697-4: RES, 0, 5%, 0.1 W, AEC-Q200 Grade 0, 0603; Manufacturer: Vishay-Dale; Power_W: 100mW; TempCo: 200 ppm/C; Value_Code: 0000; Value: 0; EIA_Code: E24; SizeX_mm: 1.6; SizeY_mm: 0.8; SizeZ_mm: 1; Value2: 0.1W; SizeArea_mm2: 1.28; AEC Qualified: Y; VDC_V: 75V; AEC Category: Q200
R4 R14 R18 R27 R31 R206 = CMP-0081856-1: RES, 0, 0%, 0.2 W, AEC-Q200 Grade 0, 0402; Manufacturer: Vishay-Dale; Value_Code: 0; SizeAreaWB_mm2: 3; SizeArea_mm2: 0.5; AEC Qualified: Y; AEC Category: Q200; Value: 0; SizeZ_mm: 0.6; Power_W: 200mW; VDC_V: 50V; Value2: 0.2W; SizeX_mm: 1
R8 R13 R22 R26 R35 R205 = CMP-0017077-1: RES, 59.0, 1%, 0.25 W, 1206; Manufacturer: Vishay-Dale; Power_W: 250mW; TempCo: 100 ppm/C; Value_Code: 59R0; U/M: EA; Value: 59.0; EIA_Code: E96; Res_ohm: 59; SizeX_mm: 3.2; SizeY_mm: 1.6; SizeZ_mm: 1.35; Value2: 0.25W; SizeArea_mm2: 5.12; VDC_V: 200V; AEC Category: Q200
R11 R24 R203 = CMP-0015444-1: RES, 120, 1%, 1 W, AEC-Q200 Grade 0, 2512; Manufacturer: Vishay-Dale; Power_W: 1W; TempCo: 100 ppm/C; Value_Code: 120R; U/M: EA; Value: 120; SizeX_mm: 6.3; SizeY_mm: 3.2; SizeZ_mm: 0.71; SizeArea_mm2: 20.16; AEC Qualified: Y; VDC_V: 500V; AEC Grade: 0; AEC Category: Q200
R210 R216 = CMP-0019378-2: RES, 910, 0.5%, 0.1 W, 0805; Manufacturer: Susumu Co Ltd; Power_W: 100mW; TempCo: 25 ppm/C; Value_Code: 910R; U/M: EA; Value: 910; SizeX_mm: 2; SizeY_mm: 1.25; SizeZ_mm: 1.45; Value2: 0.1W; SizeArea_mm2: 2.5; VDC_V: 100V; AEC Category: Q200
R213 = CMP-0021854-2: RES, 120, 1%, 0.4 W, 0805; Manufacturer: Rohm; Power_W: 400mW; TempCo: 100 ppm/C; Value_Code: 120R; U/M: EA; Value: 120; SizeX_mm: 2; SizeY_mm: 1.25; SizeZ_mm: 1.45; Value2: 0.4W; SizeArea_mm2: 2.5; VDC_V: 150V; AEC Category: Q200
T1 = CMP-0030623-1: Transformer, 105uH, TH; Manufacturer: Wurth Elektronik; Green_Lifecycle: Active; DCR_ohm: 0.06; Green_REACh: Passed; Lp: 105; Ns1toNp: 1.1; Ind_H: 105µH
U1 U4 U7 = CMP-0081957-3: 500 mW, High-Efficiency, Low-Emissions, 5 kVRMS Isolated DC-DC Converter, DVE0016A (SO-MOD-16); Alternate Manufacturer: Texas Instruments; Alternate PartNumber: UCC12050DVER; AEC Qualified: N; AEC Category: Q200; SizeX_mm: 10.3; SizeZ_mm: 2.65; SizeAreaWB_mm2: 151.29; CompType: IC; SizeArea_mm2: 106.09
U2 U5 U8 = CMP-0079585-1: Isolated CAN Transceiver With 70-V Bus Fault Protection and Flexible Data Rate, DWV0008A (SOIC-8); Alternate Manufacturer: Texas Instruments; SizeAreaWB_mm2: 105.975; SizeZ_mm: 2.8; SizeX_mm: 11.5; SizeY_mm: 5.85; SizeArea_mm2: 67.275; CompType: IC; AEC Qualified: N; AEC Category: Q200
U3 U6 U9 = CMP-0001346-1: 24-V, 2-Channel, ESD Protection With 5.7 A of 8/20 µs Surge Protection in a SOT-23 Package; Manufacturer: Texas Instruments; SizeZ_mm: 1.12mm; AEC Qualified: No; Breakdown Voltage: 25.5V; Cap_F: 1.7pF; Clamping Voltage: 38V; Direction: Bidirectional; Ipp: 16A; Number Of Channels: 2; Ppk: 90W; Standoff Height: 0.01mm; TaMax_C: +150°C; TaMin_C: -55°C; VRWM: 24V
U29 = CMP-0035533-1: Single Output LDO, 150 mA, Fixed 3.8 V Output, 2.7 to 10 V Input, with Low IQ, 5-pin SOT-23 (DBV), -40 to 125 degC, Green (RoHS & no Sb/Br); Manufacturer: Texas Instruments; SubFamily: Single Channel LDO; Vin(Min)(V): 2.7; Iout(Max)(A): 0.15; Iq(Typ)(mA): 0.08; Vdo(Typ)(mV): 300; Vout Adj(Min)(V): 3.8; Accuracy(%): 3; Vin(Max)(V): 10
U30 = CMP-0089033-2: Transformer Driver PMIC SOT-23-6; Manufacturer: Texas Instruments; CompType: IC; AEC Category: Q200; SizeZ_mm: 1.45mm; AEC Qualified: Yes
U31 = CMP-0081937-2: 5-kVRMS Reinforced and Basic Isolated RS-485/RS-422 Transceiver With Robust-EMC, DW0016B (SOIC-16); Alternate Manufacturer: Texas Instruments; SizeZ_mm: 2.65; SizeY_mm: 10.3; SizeArea_mm2: 107.12; CompType: IC; AEC Qualified: N; SizeAreaWB_mm2: 152.52; AEC Category: Q200; SizeX_mm: 10.4
U33 = CMP-0002019-2: Asymmetrical TVS Diode for Extended Common-Mode RS-485, SOT-23; Manufacturer: Semtech; Value: 7V, 12V; SizeX_mm: 2.5; SizeY_mm: 3; SizeZ_mm: 1.1; SizeArea_mm2: 7.5; SizeAreaWB_mm2: 14

## Sheet BCU_HARDWARE.SchDoc
size A3; Date: Not shown in title block; ApprovedBy: Not shown in title block; CheckedBy: Not shown in title block; Author: Not shown in title block; CompanyName: Not shown in title block; Engineer: Not shown in title block; Organization: Not shown in title block; Address1: Not shown in title block; Address2: Not shown in title block; Address3: Not shown in title block; Address4: Not shown in title block; DocumentNumber: 1; Revision: Use project parameter SCH_Rev; SheetNumber: 8; SheetTotal: 8; PageSetup: Record=PageOptions¦CenterHorizontal=True¦CenterVertical=True¦PrintScale=0.69¦XCorrection=1.00¦YCorrection=1.00¦PrintKind=0¦BorderSize=5000000¦LeftOffset=0¦BottomOffset=0¦Orientation=2¦PaperLength=1000¦PaperWidth=1000¦Scale=100¦PaperSource=15¦PrintQuality=600¦MediaType=1¦DitherType=10¦PaperKind=Letter¦PrintScaleMode=1
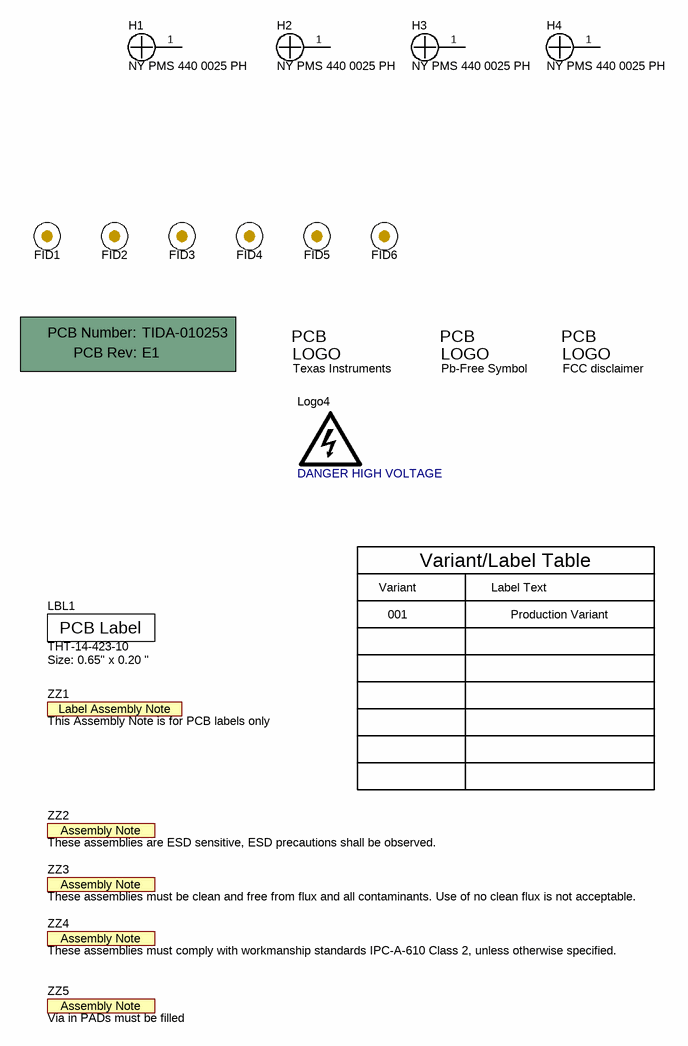
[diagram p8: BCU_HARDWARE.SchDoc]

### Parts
!PCB1  Printed Circuit Board  (value not drawn)  (mechanical)
FID1  Fiducial  [Fiducial10-20]  (value not drawn)
FID2  Fiducial  [Fiducial10-20]  (value not drawn)
FID3  Fiducial  [Fiducial10-20]  (value not drawn)
FID4  Fiducial  [Fiducial10-20]  (value not drawn)
FID5  Fiducial  [Fiducial10-20]  (value not drawn)
FID6  Fiducial  [Fiducial10-20]  (value not drawn)
H1  NY PMS 440 0025 PH  [NY PMS 440 0025 PH]
H2  NY PMS 440 0025 PH  [NY PMS 440 0025 PH]
H3  NY PMS 440 0025 PH  [NY PMS 440 0025 PH]
H4  NY PMS 440 0025 PH  [NY PMS 440 0025 PH]
LBL1  THT-14-423-10  Note: Size: 0.65" x 0.20 "  [Label_650x200]
Logo1  Texas Instruments  [TI_Stacked_Overlay_Small]  (no BOM)
Logo2  Pb-Free Symbol  [Pb-Free_Overlay_Small]  (no BOM)
Logo3  FCC disclaimer  [FCC_disclaimer]  (no BOM)
Logo4  DANGER HIGH VOLTAGE  [IEC_HighVoltage_Small]  (no BOM)
ZZ1  This Assembly Note is for PCB labels only  [AssemblyNoteLabel]  (no BOM)
ZZ2  These assemblies are ESD sensitive, ESD precautions shall be observed.  [AssemblyNote]  (no BOM)
ZZ3  These assemblies must be clean and free from flux and all contaminants. Use of no clean flux is not acceptable.  [AssemblyNote]  (no BOM)
ZZ4  These assemblies must comply with workmanship standards IPC-A-610 Class 2, unless otherwise specified.  [AssemblyNote]  (no BOM)
ZZ5  Via in PADs must be filled  [AssemblyNote]  (no BOM)

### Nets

Not connected (* = marked no-connect by the designer): H1 1; H2 1; H3 1; H4 1

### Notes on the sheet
- Variant/Label Table
- Variant
- 001
- Label Text
- Production Variant

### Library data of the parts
!PCB1 = CMP-0003618-2: Manufacturer: Any; PartNumber: TIDA-010253
FID1-FID6 = CMP-0077181-1: Fiducial mark.  There is nothing to buy or mount.
H1-H4 = CMP-0003617-1: Machine Screw, Round, #4-40 x 1/4, Nylon, Philips panhead; Manufacturer: B&F Fastener Supply; CompType: Hardware
LBL1 = CMP-0003625-1: Thermal Transfer Printable Labels, 0.650" W x 0.200" H - 10,000 per roll; Manufacturer: Brady; CompType: Label
Logo1 = CMP-0074838-1: Texas Instrument Corporate Signature; SymbolCreator: a0412235; Lib Reference: TI_Logo; Library Reference: Logo
Logo2 = CMP-0074839-1: SymbolCreator: a0412235; Library Reference: Logo
Logo3 = CMP-0074847-1: FCC_disclaimer; Library Reference: Logo
Logo4 = CMP-0074835-1: IEC 61010-1 High Voltage Warning; SymbolCreator: a0412235
ZZ1 = CMP-0003616-3
ZZ2 = CMP-0077236-1
ZZ3 = CMP-0077237-1
ZZ4 = CMP-0077238-1
ZZ5 = CMP-0077238-1: These assemblies must comply with workmanship standards IPC-A-610 Class 2, unless otherwise specified.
